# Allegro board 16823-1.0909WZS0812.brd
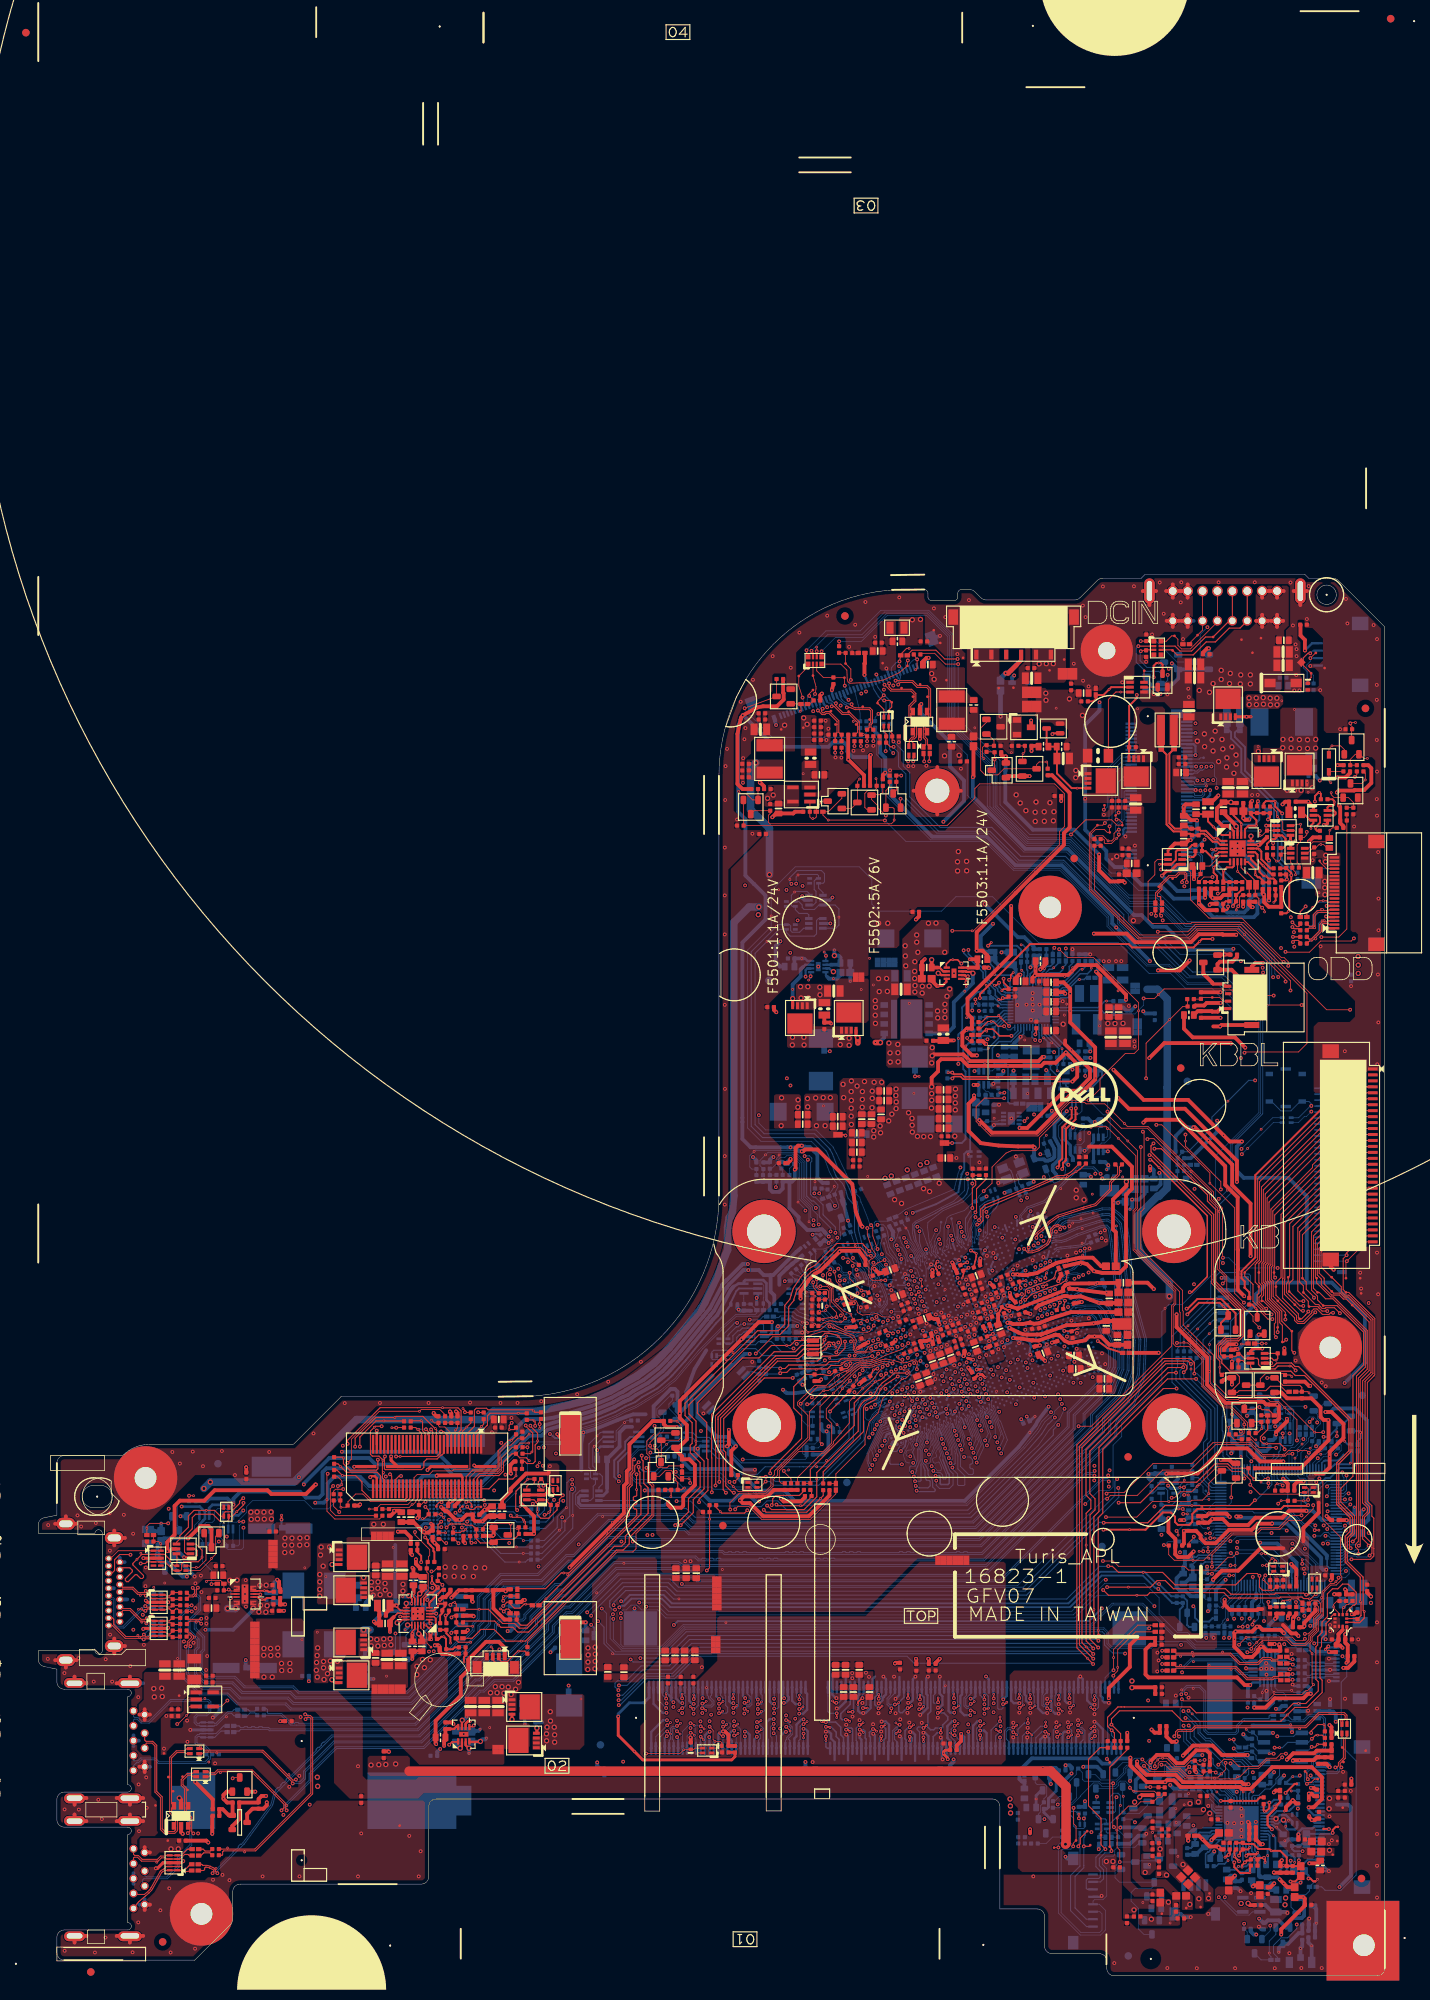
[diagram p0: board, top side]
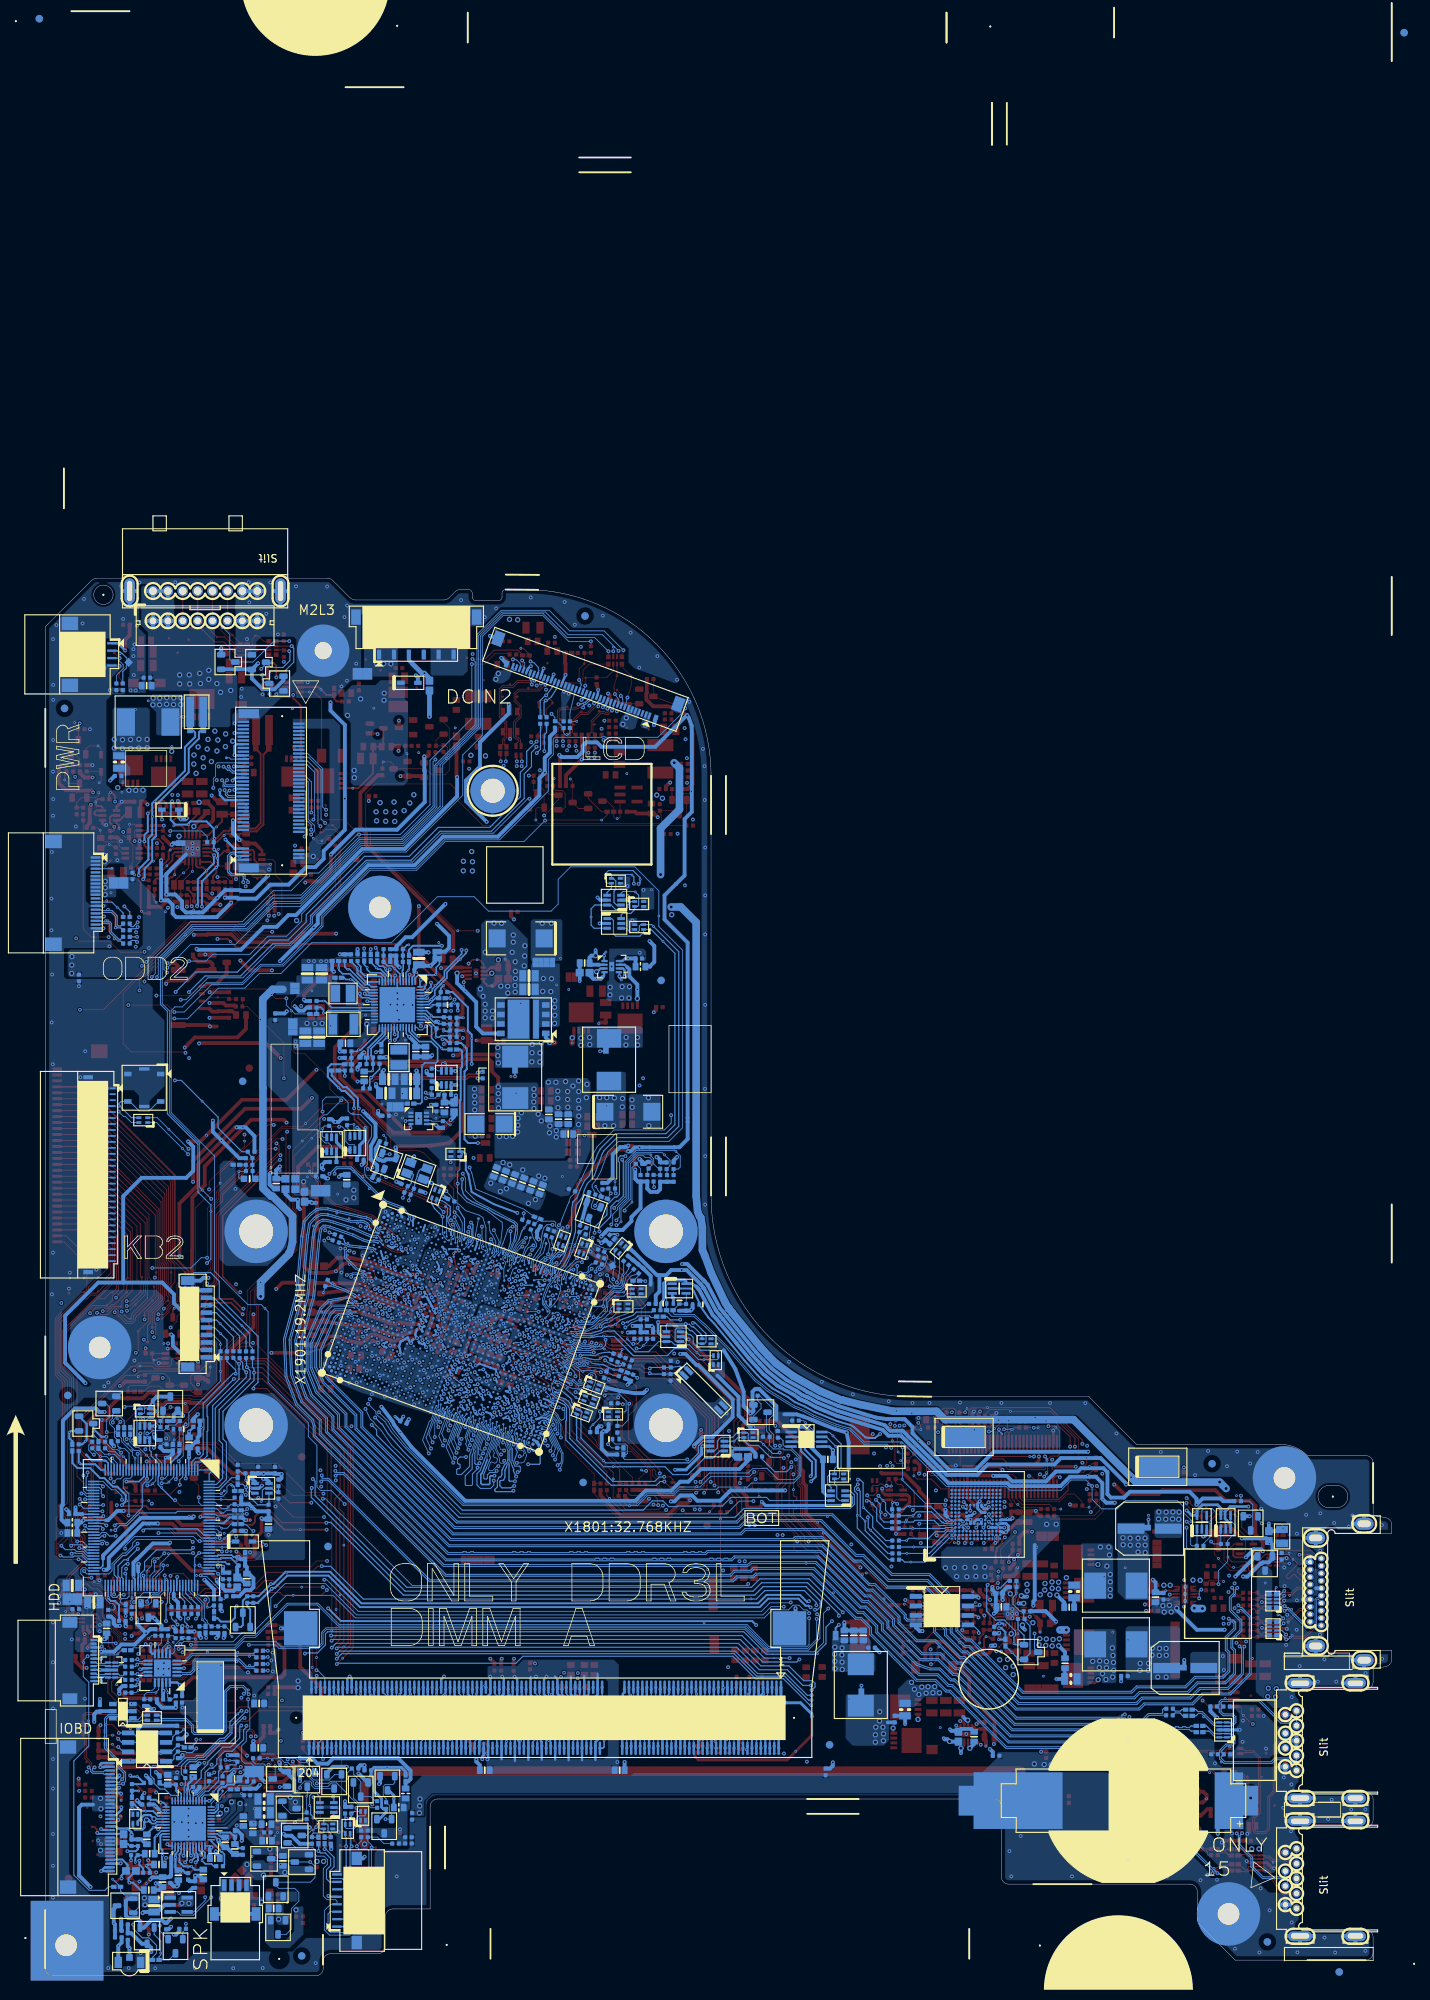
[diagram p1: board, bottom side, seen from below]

Outline 180.7 x 188 mm; copper layers: TOP, L2VCC, L3, L4, L5GND, BOTTOM. Coordinates in mm from the lower left corner of the outline.
Outline path: 0,60.48 0,59.35 7.6,59.35 arc(8.1,59.85) 8.6,59.35 8.6,43.65 arc(8.1,43.15) 7.6,43.65 0,43.65 0,42.47 arc(0.23,41.84) 0.8,41.49 2.5,41.15 2.5,39.45 arc(2.79,38.74) 3.5,38.45 11.99,38.45 arc(12.49,37.95) 11.99,37.45 11.99,25.65 arc(12.49,25.15) 11.99,24.65 3.5,24.65 arc(2.79,24.36) 2.5,23.65 2.5,20.95 arc(2.79,20.24) 3.5,19.95 11.99,19.95 arc(12.49,19.45) 11.99,18.95 11.99,7.15 arc(12.49,6.65) 11.99,6.15 3.5,6.15 arc(2.79,5.86) 2.5,5.15 2.5,3.1 arc(2.79,2.39) 3.5,2.1 21,2.1 25.81,6.91 arc(26.02,7.23) 26.1,7.61 26.1,11.3 arc(26.39,12.01) 27.1,12.3 51.4,12.3 arc(52.11,12.59) 52.4,13.3 52.4,22.72 arc(52.69,23.43) 53.4,23.72 128.05,23.72 arc(128.76,23.43) 129.05,22.72 129.05,8.97 134.05,8.97 arc(134.76,8.68) 135.05,7.97 135.05,3.97 arc(135.34,3.26) 136.05,2.97 142.4,2.97 arc(143.11,2.68) 143.4,1.97 143.4,1 arc(143.69,0.29) 144.4,0 179.7,0 arc(180.41,0.29) 180.7,1 180.7,181 174.49,187.21 arc(174.17,187.42) 173.79,187.5 170.5,187.5 170,188 148.5,188 148,187.5 142.81,187.5 arc(142.43,187.42) 142.11,187.21 139.79,184.89 arc(139.47,184.68) 139.09,184.6 127.21,184.6 arc(126.83,184.68) 126.51,184.89 125.69,185.71 arc(125.37,185.92) 124.99,186 123.9,186 arc(123.55,185.85) 123.4,185.5 123.4,185 arc(123.25,184.65) 122.9,184.5 119.9,184.5 arc(119.55,184.65) 119.4,185 119.4,185.5 arc(119.25,185.85) 118.9,186 116.35,186 arc(98.67,178.68) 91.35,161 91.35,104.7 arc(83.44,85.61) 64.35,77.7 40.63,77.7 34.23,71.3 14.9,71.3 arc(12.96,70.91) 11.33,69.8 3.5,69.8 arc(2.79,69.51) 2.5,68.8 2.5,61.8 0.8,61.46 arc(0.23,61.11) 0,60.48 ; 7.4,65.8 8.4,65.8 arc(9.9,64.3) 8.4,62.8 7.4,62.8 arc(5.9,64.3) 7.4,65.8 ; 95.15,99.88 arc(97.4,102.13) 99.65,99.88 arc(97.4,97.63) 95.15,99.88 ; 95.15,73.88 arc(97.4,76.13) 99.65,73.88 arc(97.4,71.63) 95.15,73.88 ; 150.15,99.88 arc(152.4,102.13) 154.65,99.88 arc(152.4,97.63) 150.15,99.88 ; 150.15,73.88 arc(152.4,76.13) 154.65,73.88 arc(152.4,71.63) 150.15,73.88 ; 171.6,185.3 arc(172.9,186.6) 174.2,185.3 arc(172.9,184) 171.6,185.3

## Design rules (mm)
constraint set DEFAULT: min track width 0.127, pair gap 0.102
net group ALWON: nets 3V_S5_EN 5V_S5_EN
net group BT_USB20_N: nets BT_USB20_N USB_CON_PN5
net group BT_USB20_P: nets BT_USB20_P USB_CON_PP5
net group CARD1_USB20_N: nets CARD1_USB20_N USB_CON_PN6
net group CARD1_USB20_P: nets CARD1_USB20_P USB_CON_PP6
net group CHARGER_10MIL_VIA_25MIL: nets PWR_CHG_CSON_1 PWR_CHG_CSOP_1
net group COMP_DRAM: nets SM_RCOMP_0 SM_RCOMP_1
net group COMP_USB: nets USB_RCOMP USB_SSIC_RCOMP
net group DDR3_CHA_CTRL-MW: nets M_A_CS#0 M_A_CS#1
net group DDR3L_CHA_CTRL_CKE: nets M_A_CKE0 M_A_CKE1
net group DDR3L_CHA_CTRL_ODT: nets M_A_ODT0 M_A_ODT1
net group EC_SPI_CLK: nets EC_SPI_CLK SPI_CLK_ROM
net group EC_SPI_CS0#: nets EC_SPI_CS0# SPI_CS_ROM_N0_R
net group EC_SPI_MISO: nets EC_SPI_MISO SPI1_SO_ROM_R
net group EC_SPI_MOSI: nets EC_SPI_MOSI SPI_SI_ROM
net group EDP_AUX_CON_N: nets EDP_AUX_CON_N EDP_AUX_CPU_N
net group EDP_AUX_CON_P: nets EDP_AUX_CON_P EDP_AUX_CPU_P
net group EDP_TX_CON_N0: nets EDP_TX_CON_N0 EDP_TX_CPU_N0
net group EDP_TX_CON_N1: nets EDP_TX_CON_N1 EDP_TX_CPU_N1
net group EDP_TX_CON_P0: nets EDP_TX_CON_P0 EDP_TX_CPU_P0
net group EDP_TX_CON_P1: nets EDP_TX_CON_P1 EDP_TX_CPU_P1
net group GND_100: nets EC_AGND JDREF
net group GND_400: nets GND_R1 GND_R2
net group HDA_BITCLK_CPU: nets HDA_BITCLK_CPU HDA_CODEC_BITCLK
net group HDA_CODEC_SDIN0: nets HDA_CODEC_SDIN0 HDA_SDIN0_CPU
net group HDA_CODEC_SDOUT: nets HDA_CODEC_SDOUT HDA_SDOUT_CPU
net group HDA_CODEC_SYNC: nets HDA_CODEC_SYNC HDA_SYNC_CPU
net group HDMI_CLK_CON: nets HDMI_CLK_CON HDMI_CLK_CPU
net group HDMI_DATA_CON: nets HDMI_DATA_CON HDMI_DATA_CPU
net group HDMI_DATA_CON_N0: nets HDMI_DATA_CON_N0 HDMI_DATA_CPU_N0
net group HDMI_DATA_CON_N1: nets HDMI_DATA_CON_N1 HDMI_DATA_CPU_N1
net group HDMI_DATA_CON_N2: nets HDMI_DATA_CON_N2 HDMI_DATA_CPU_N2
net group HDMI_DATA_CON_N3: nets HDMI_DATA_CON_N3 HDMI_DATA_CPU_N3
net group HDMI_DATA_CON_P0: nets HDMI_DATA_CON_P0 HDMI_DATA_CPU_P0
net group HDMI_DATA_CON_P1: nets HDMI_DATA_CON_P1 HDMI_DATA_CPU_P1
net group HDMI_DATA_CON_P2: nets HDMI_DATA_CON_P2 HDMI_DATA_CPU_P2
net group HDMI_DATA_CON_P3: nets HDMI_DATA_CON_P3 HDMI_DATA_CPU_P3
net group I2C_DATA: nets DBG_I2C_SDA_LB I2C7_SDA_CPU
net group ISH_GP: nets GSENSOR_CS GSENSOR_SDO
net group OTG: nets USB2_OTG_ID USB2_VBUS_SNS
net group OTHER_4_CLASS: nets 5V_DDC_HDMI1 5V_DDC_HDMI2
net group OTHER_10: nets CAP_LED CAP_LED_Q
net group POWER_15M: nets 3D3V_TP_S5_R Q6205_Q
net group PSID_4M: nets PS_ID PSID
net group SMBUS_50-MWS: nets TP_I2C_CLK_C TP_I2C_DATA_C
net group SPI_CLK_ROM_CPU: nets SPI_CLK_ROM_CPU SPI_CLK_ROM_R1
net group SPI_CS_CPU_N0: nets SPI_CS_CPU_N0 SPI_CS_ROM_N0_R1
net group SPI_HOLD_ROM: nets SPI_HOLD_ROM SPI_HOLD_ROM_R
net group SPI_SI_ROM_CPU: nets SPI_SI_ROM_CPU SPI_SI_ROM_R1
net group SPI_SO_ROM: nets SPI_SO_ROM SPI_SO_ROM_R1
net group SPI_WP_ROM: nets SPI_WP_ROM SPI_WP_ROM_R
net group TS_USB20_N: nets TS_USB20_N USB_PN4_TPNL
net group TS_USB20_P: nets TS_USB20_P USB_PP4_TPNL
net group USB1_USB20_N: nets USB1_USB20_N USB_CON_PN1
net group USB1_USB20_P: nets USB1_USB20_P USB_CON_PP1
net group USB1_USB30_RX_CON_N: nets USB1_USB30_RX_CON_N USB1_USB30_RX_N
net group USB1_USB30_RX_CON_P: nets USB1_USB30_RX_CON_P USB1_USB30_RX_P
net group USB2_CON_USB20_N: nets USB2_CON_USB20_N USB2_USB20_N
net group USB2_CON_USB20_P: nets USB2_CON_USB20_P USB2_USB20_P
net group USB2_USB30_RX_CON_N: nets USB2_USB30_RX_CON_N USB2_USB30_RX_N
net group USB2_USB30_RX_CON_P: nets USB2_USB30_RX_CON_P USB2_USB30_RX_P
net group USB3_CON_USB20_N: nets USB3_CON_USB20_N USB3_USB20_N
net group USB3_CON_USB20_P: nets USB3_CON_USB20_P USB3_USB20_P
net group WLAN_CPU_TX_N: nets WLAN_CPU_TX_N WLAN_PCIE_TX_N
net group WLAN_CPU_TX_P: nets WLAN_CPU_TX_P WLAN_PCIE_TX_P
net group BKLT_EDP-MW: nets BKLT_CTRL EC_BRIGHTNESS EDP_BLCTRL_CPU EDP_VDDEN_CPU L_BKLT_CTRL L_BKLT_CTRL_B L_BKLT_EN_EC LCD_BRIGHTNESS LVDS_VDD_EN LVDS_VDD_EN_B LVDS_VDD_EN_R
net group CHARGER_10MIL: nets BOOST_MODE# PWR_CHG_CMPIN_R PWR_CHG_CMPIN_RR PWR_CHG_IFAULT PWR_CHG_ILIM PWR_CHG_IOUT
net group CHARGER_20MIL_CLASS: nets PWR_CHG_BTST_R
net group CLK_19D2M_32D768_CPU-MW: nets SUSCLK XTL_19D2M_X1_CPU XTL_19D2M_X2_CPU XTL_32K_X1_CPU XTL_32K_X2_CPU
net group CLK_LPC-MW: nets CLK_TP_SIO LPC_AD_CPU_P0 LPC_AD_CPU_P1 LPC_CLK_CPU_P0 LPC_CLK_CPU_P1 LPC_CLK_DBG LPC_CLK_KBC
net group CMP: nets PURE_HW_SHUTDOWN# THERM_SYS_SHDN# VD_IN1 VD_OUT1#
net group CPU_SIDE-MW: nets 1D8V_S0_EN AC_PRESENT_KBC AD_IA DBC_EN DBC_EN_C DBC_EN_R DDR_DRAMRST# DDR_DRAMRST#_R EDP_BLEN_CPU EDP_HPD_CPU_D GP_SSP0_FS1 H_PROCHOT_EC HDMI_DET_CPU# HDMI_HPD_G HPD_HDMI_CON INT_TP#_CONN PCIE_WAKE0_CPU PCIE_WAKE0_CPU# PCIE_WAKE1_CPU PCIE_WAKE2_CPU PCIE_WAKE3_CPU PM_PWRBTN# PM_PWRBTN#_CPU PM_RSMRST# PM_SLP_S3# PM_SLP_S4# PM_WAKE# PROCHOT#_CPU_R RUN_ON# RUN_ON_R SIO_EXT_SCI# SIO_EXT_SMI# SIO_SLP_S3# SIO_SLP_S4# SOC_PWROK_CPU SOC_RUNTIME_SCI# SUS_PWRDN_ACK SYS_PWROK SYS_PWROK_G TP_IN#_CPU TP_IN#_CPU_D WIFI_RF_EN WLAN_CLKREQ_D
net group DDR3_CHA_CMD-MW: nets M_A_A0 M_A_A1 M_A_A2 M_A_A3 M_A_A4 M_A_A5 M_A_A6 M_A_A7 M_A_A8 M_A_A9 M_A_A10 M_A_A11 M_A_A12 M_A_A13 M_A_A14 M_A_A15
net group DDR3_CHA_CMD_OTHER: nets M_A_CAS# M_A_RAS# M_A_WE#
net group DDR3_CHA_DATA-MW: nets M_A_DQ56 M_A_DQ57 M_A_DQ58 M_A_DQ59 M_A_DQ60 M_A_DQ61 M_A_DQ62 M_A_DQ63
net group DDR3L_CHA_CMD_BS: nets M_A_BS0 M_A_BS1 M_A_BS2
net group DDR3L_CHA_DATA_0_7: nets M_A_DQ0 M_A_DQ1 M_A_DQ2 M_A_DQ3 M_A_DQ4 M_A_DQ5 M_A_DQ6 M_A_DQ7
net group DDR3L_CHA_DATA_8_15: nets M_A_DQ8 M_A_DQ9 M_A_DQ10 M_A_DQ11 M_A_DQ12 M_A_DQ13 M_A_DQ14 M_A_DQ15
net group DDR3L_CHA_DATA_16_23: nets M_A_DQ16 M_A_DQ17 M_A_DQ18 M_A_DQ19 M_A_DQ20 M_A_DQ21 M_A_DQ22 M_A_DQ23
net group DDR3L_CHA_DATA_24_31: nets M_A_DQ24 M_A_DQ25 M_A_DQ26 M_A_DQ27 M_A_DQ28 M_A_DQ29 M_A_DQ30 M_A_DQ31
net group DDR3L_CHA_DATA_32_39: nets M_A_DQ32 M_A_DQ33 M_A_DQ34 M_A_DQ35 M_A_DQ36 M_A_DQ37 M_A_DQ38 M_A_DQ39
net group DDR3L_CHA_DATA_40_47: nets M_A_DQ40 M_A_DQ41 M_A_DQ42 M_A_DQ43 M_A_DQ44 M_A_DQ45 M_A_DQ46 M_A_DQ47
net group DDR3L_CHA_DATA_48_55: nets M_A_DQ48 M_A_DQ49 M_A_DQ50 M_A_DQ51 M_A_DQ52 M_A_DQ53 M_A_DQ54 M_A_DQ55
net group DDR_VREF: nets M_A_VREFCA_CPU M_A_VREFDQ_CPU VREF_CA VREF_DQ
net group EMMC_DATA_CMD: nets EMMC_CMD EMMC_CMD_R EMMC_DATA_0 EMMC_DATA_0_R EMMC_DATA_1 EMMC_DATA_1_R EMMC_DATA_2 EMMC_DATA_2_R EMMC_DATA_3 EMMC_DATA_3_R EMMC_DATA_4 EMMC_DATA_4_R EMMC_DATA_5 EMMC_DATA_5_R EMMC_DATA_6 EMMC_DATA_6_R EMMC_DATA_7 EMMC_DATA_7_R EMMC_E9 EMMC_E10 EMMC_F10 EMMC_K10 EMMC_RESET# EMMC_RST_N EMMC_VDDI
net group EMMC_DATA_CMD_CLK: nets EMMC_CLK EMMC_CLK_R EMMC_CLK_RC EMMC_RCLK EMMC_RCLK_R EMMC_RCLK_RC
net group EMMC_RCOMP: nets EMMC_RCOMP
net group FAN_TACH: nets FAN_TACH1
net group FFS: nets HDD_FALL_INT
net group GND_20: nets MIC_GND
net group GPIO: nets DBG_PMU_RSTBTN DBG_TARGET_PRESENT_N DIMM1_SA0 DIMM1_SA1 GP_SSP2_TXD GPIO34_CPU GPIO35_CPU GPIO40_CPU GPIO82_CPU HDD_DEVSLP_R INTRUDER JTAG_PMODE KB_DET# PLT_RST#_DEBUG PM_BATLOW# PM_RSTBTN# PM_SLP_S0# PM_SUS_STAT# PM_SUSCLK SATA_LED#_CPU TP_INT#_EC TS#_DIMM0_1
net group HDD_SATA_RX_N: nets HDD_SATA_RX_N SATA3_DRX_CTX_N0 SATA3_DRX_CTX_N0_R SATA3_PRX_DTX_N0_L SATA_RXN0_C
net group HDD_SATA_RX_P: nets HDD_SATA_RX_P SATA3_DRX_CTX_P0 SATA3_DRX_CTX_P0_R SATA3_PRX_DTX_P0_L SATA_RXP0_C
net group HDD_SATA_TX_N: nets HDD_SATA_TX_N SATA3_DTX_CRX_N0 SATA3_DTX_CRX_N0_R SATA3_PTX_DRX_N0_R SATA_TXN0_C
net group HDD_SATA_TX_P: nets HDD_SATA_TX_P SATA3_DTX_CRX_P0 SATA3_DTX_CRX_P0_R SATA3_PTX_DRX_P0_R SATA_TXP0_C
net group I2C_CLK: nets DBG_I2C_SCL_LB I2C7_SCL_CPU PMIC_I2C_SCL
net group I2C_CLK_CLASS: nets I2C3_SCL_CPU TP_I2C_CLK TP_I2C_CLK_D
net group I2C_DATA_CLASS: nets I2C3_SDA_CPU TP_I2C_DATA TP_I2C_DATA_D
net group KB: nets KSI0 KSI1 KSI2 KSI3 KSI4 KSI5 KSI6 KSI7 KSO0 KSO1 KSO2 KSO3 KSO4 KSO5 KSO6 KSO7 KSO8 KSO9 KSO10 KSO11 KSO12 KSO13 KSO14 KSO15 KSO16
net group KBC_XTAL: nets DBG_CFG6
net group LED: nets BATT_WHITE_LED# BATT_WHITE_LED_R# CHG_AMBER_LED# CHG_AMBER_LED_R#
net group LED_20MIL: nets AMBER_LED_BAT BAT_AMBER BAT_WHITE WHITE_LED_BAT
net group LPC: nets CLKRUN# INT_SERIRQ INT_SERIRQ_KBC INT_SERIRQ_OE LPC_AD_CPU_P2 LPC_AD_CPU_P3 LPC_FRAME#_CPU LPC_FRAME#_DEBUG LPC_LAD0_C LPC_LAD0_R LPC_LAD1_C LPC_LAD1_R LPC_LAD2_C LPC_LAD2_R LPC_LAD3_C LPC_LAD3_R PM_CLKRUN#_EC SERIRQ
net group NOISE_SENSITIVE_GPIO: nets DBG_PMU_PLTRST H_PROCHOT# PLT_RST# PLTRST#_CPU
net group OTHER_4: nets 3V_5V_PWRGD AC_DIS AC_IN# AC_IN_KBC AC_IN_KBC# AD_IA_HW AD_IA_HW2 ALERT# BLON_OUT_C BLUETOOTH_EN_KBC BOOT_HALT_N CAP_LED# CAP_LED_R# COMBO-GPI DBG_PMU_PWRBTN DC_DET DP_HPD0_C DP_HPD0_G DVSS E51_RX1 E51_RX2 E51_TX1 E51_TX2 EC_SMI# EC_SMI#_SOC ECRST# H_A20GATE H_RCIN# INT_SPK_1 INT_SPK_R KBC_ON#_GATE KBC_ON#_GATE_L KBC_PECI KBC_PWRBTN# LCD_TST LCD_TST_C LCD_TST_EN LCD_TST_KBC LID_CLOSE# LVDS_VDD_EN_KBC PANEL_BKEN_EC PANEL_BKEN_EC_KBC PBAT_PRES1# PBAT_PRES# PCB_VER_AD PD4404_A PD4404_K PMIC_EN_KBC PMIC_PWRGD PMIC_THERMTRIP# PQ3802_1 PQ4408_2 PQ4408_6 PQ4409_C PQ4409_E PQ4410_2 PQ4410_3 PQ4410_5 PQ4410_6 PQ4414_D PQ4414_G PRO_SP PROJECT_ID1 PROJECT_ID2 PSID_DISABLE#_R_C PSL_IN1# PSL_IN2# PSL_OUT# PTP_DIS# RTC_DET# SATA3_EQ1_HDD SATA3_EQ2_HDD SATA_LED SD_AMP SD_AMP# SD_AMP_R SIO_SLP_S3 SIO_SLP_S4 SUS_PWR_ACK_R SYS_PRES1# T_CRIT# TOUCH_INT_CPU TOUCH_PANEL_EN TOUCH_RST_CPU TP_DISABLE#_R TP_EN# TP_ON#_GATE TPNL_EN TRST_PD UART2_RTS# USB_OC#0 USB_OC#1 USB_PWR_EN#
net group OTHER_4_2: nets 3V_EN AC_PRESENT BOARD_ID2 CT#_U4002 EC_MUTE# GFX_CLKREQ_CPU# HDD_DEW1 HDD_DEW2 KB_LED_BL_DET_R KB_LED_DET_C LAN_CLKREQ_CPU# LID_CLOSE#_C NMI_SMI_DBG#_CPU PANEL_SIZE_ID PANEL_SIZE_ID_CONN PCIE_CLKREQ1_CPU# PD# PEG_CLKREQ_WLAN# PMIC_THERMTRIP#_KBC PWR_5V_VCLK RSMRST#_KBC RSMRST_IN_PMIC SATA3_DE1_HDD SATA3_DE2_HDD SATA_DEVSLP_HDD_CPU TP_RESET VRAM_ID1 WLAN_CLKREQ_CPU#
net group OTHER_4MIL_8MIL: nets E51_TXD
net group OTHER_6: nets S5_ENABLE
net group OTHER_8: nets COMP2 COMP2_P FB_VNN FBL_VCCGI FBL_VDDQ FBL_VNN PMIC_IRQ PMIC_PWROK_KBC PMIC_RSMRST#
net group OTHER_12: nets CBN CBP CPVEE LDO1_CAP LDO2_CAP LDO3_CAP V3D3_STB
net group P27_AUDIO_ANALOG: nets AUD_HP1_JACK_L AUD_HP1_JACK_L1 AUD_HP1_JACK_R AUD_HP1_JACK_R1 AUD_PC_BEEP_3246 AUD_PC_BEEP_C AUD_PC_BEEP_R AUD_PORTA_L_R_B AUD_PORTA_R_R_B AUD_SENSE AUD_SENSE_A AUD_VREF BEEP HDA_SPKR HDA_SPKR_R JACK_PLUG KBC_BEEP_R LINE1-L_C LINE1-L_R LINE1_L LINE1_R LINE1_VREFO_L LINE1_VREFO_R
net group PLATFORM: nets CAMERA_DET# CAMERA_DET#_R KBC_PWRBTN#_C PQ3809_D SATA_ODD_DA#_C SATA_ODD_DA#_C2 SATA_ODD_PRSNT# SATA_ODD_PRSNT#_CPU SATA_ODD_PRSNT#_D SATA_ODD_PRSNT#_R SATA_ODD_PRSNT#_R2
net group POWER_8: nets PWR_1D8V_FB PWR_1D24V_FB PWR_COMP2 PWR_CSDIS1 PWR_CSDIS2 PWR_DDRSEL PWR_FB2 PWR_IRQ# PWR_OCSET6 PWR_PMIC_EN PWR_PWROK PWR_RSMEST# PWR_SLP_S0# PWR_SLP_S3# PWR_SLP_S4# PWR_THERMTRIP# PWR_VCCGI_EN PWR_VCCGI_ISEN PWR_VCCGI_PWM PWR_VCCRAM_FB PWR_VDDQ_EN PWR_VDDQ_FB PWR_VDDQ_PWM PWR_VIN_CT PWR_VNN_EN PWR_VNN_FB PWR_VNN_PWM PWR_VO2 PWR_VSS PWR_VSYS PWR_VTT_SEN
net group POWER_8_CLASS: nets PWR_VCCGI_SNUB PWR_VDDQ_SNUB PWR_VNN_SNUB
net group POWER_10: nets 3D3V_S0_CT 5V_S0_CT +3.3V_1.8V_DVDD-IO +3V_1D5V_AVDD +3V_AVDD FAN1_DAC_1 MIC_CAP PWR_3D3V_CS2 PWR_3D3V_EN2 PWR_3D3V_FB2 PWR_3D3V_FB2_R PWR_5V_CS1 PWR_5V_FB1_R PWR_CHG_ACDET PWR_CHG_ACOK PWR_CHG_CMPIN PWR_CHG_REGN PWR_CHG_VCC
net group POWER_10_CLASS: nets PWR_CHG_BTST
net group POWER_10_VIA: nets AD+_G_1 AD+_G_2 DC_IN_D PWR_CHG_SRN PWR_CHG_SRP
net group POWER_10M_POWER: nets 3V_FEEDBACK AC_IN#_G AD_OFF_L AD_OFF_R PWR_5V_EN1 PWR_5V_FB1 PWR_CHG_CMPOUT
net group POWER_20: nets 0D675V_S0_DISCHG 1D8V_S0_DISCHG 1D35V_S3_DISCHG 3D3V_G_VDD_S0 3D3V_VCCRTC +5V_AVDD +RTC_PWR EC_AVCC EC_VCC1V8 EC_VTT EMMC_VCC EMMC_VCCQ KBC_VCC KBC_VCC1D8V KBC_VCORF PWR_3D3V_VBST2 PWR_3D3V_VBST2_1 PWR_5V_VBST1 PWR_5V_VBST1_1 PWR_5V_VO1 PWR_VCC PWR_VCCGI_VCC PWR_VDDQ_VCC PWR_VNN_VCC RTC_DET#_G SPI1_VCC_1D8V SPI_VCC_1D8V
net group POWER_20M_POWER: nets 3D3V_PWR_2 5V_PWR_2 +5V_KB_BL BKLGT_PWM CPVDD KB_BL_CTRL# PWR_3D3V_SNUB PWR_5V_SNUB
net group POWER_30_CLASS: nets PWR_VCCGI_BOOT PWR_VCCGI_BOOT_A PWR_VCCGI_HG PWR_VCCGI_LG PWR_VDDQ_BOOT PWR_VDDQ_BOOT_A PWR_VDDQ_HG PWR_VDDQ_LG PWR_VNN_BOOT PWR_VNN_BOOT_A PWR_VNN_HG PWR_VNN_LG
net group POWER_40M_POWER: nets 5V_HDMI_R_S0 PWR_3D3V_DRVH2 PWR_5V_DRVH1
net group POWER_60: nets 1D24V_AUD_ISH_PLL 1D24V_DSI_CSI 1D24V_GLML 1D24V_USB2 1P8U 3D3V_1D8V_GSEN2 PWR_VTT
net group POWER_120: nets 1D05V_FHV0 1D05V_FHV1 1D05V_FUSE
net group PSID_25MIL: nets PS_ID_R
net group PWR_PHA: nets PWR_VCCGI_PHA PWR_VDDQ_PHA PWR_VNN_PHA
net group RCOMP: nets GPIO_RCOMP MCSI_RCOMP_1 MCSI_RCOMP_2 MDSI_RCOMP PCIE_REF_CLK_RCOMP PMU_RCOMP
net group REF_10: nets KBC_VBKUP
net group RTC-MW: nets BVCCRTC_EXTPAD
net group SENSOR: nets FALL_INT2 FFS_INT2 FFS_INT2_Q
net group SIGNAL_V_F_4MIL: nets HDD_DEVSLP
net group SIGNAL_V_F_5MIL: nets DGPU_PWROK
net group SMBUS_CLK-MW: nets AVS_DMIC_CLK AVS_DMIC_DATA DMIC_CLK DMIC_CLK_C DMIC_CLK_C# DMIC_CLK_D DMIC_CLK_R DMIC_DATA_C# DMIC_DATA_D NCT_CLK PBAT_SMBCLK1 PCH_SMB_CLK PWR_CHG_BAT_SCL SMB_ALERT#_CPU SMB_CLK SMB_CLK_CPU SMBCLK1 TP_CLK_C
net group SMBUS_DAT-MW: nets DAT_TP_SIO DMIC_DATA DMIC_DATA_C DMIC_DATA_R NCT_DATA PBAT_SMBDAT1 PCH_SMB_DATA PMIC_I2C_SDA PWR_CHG_BAT_SDA SMB_DATA SMB_DATA_CPU SMBDA1 TP_DATA_C
net group SPI_SIDE: nets SPI1_HOLD_ROM_R SPI1_WP_ROM_R UART2_RXD UART2_TXD
net group STRAP_PIN: nets DFX_MSR_STRAP GPIO36_VCCIO_LEVEL GPIO39_TXE_BPS GPIO43_EMMC_BOOT GPIO44_SPI_BOOT GPIO47_DNXFW GPIO78_SMB_LEVEL GPIO88_PMU_LEVEL GPIO92_SMB_NRB GPIO110_LPC_LEVEL GPIO111_BBS GPIO118_FLASH_OVR GPIO120_BIOS_SWAP ME_FWP_EC_CPU
net group T8: nets VD_IN1_C
net group THERM_10MIL: nets VD1_EN#
net group USB1_USB30_TX_CON_N: nets USB1_USB30_TX_CON_N USB1_USB30_TX_N USB1_USB30_TX_N_R
net group USB1_USB30_TX_CON_P: nets USB1_USB30_TX_CON_P USB1_USB30_TX_P USB1_USB30_TX_P_R
net group USB2_USB30_TX_CON_N: nets USB2_USB30_TX_CON_N USB2_USB30_TX_N USB2_USB30_TX_N_R
net group USB2_USB30_TX_CON_P: nets USB2_USB30_TX_CON_P USB2_USB30_TX_P USB2_USB30_TX_P_R
net group XDP-MW: nets CFG0 CFG1 CFG2 CFG3 CFG4 CFG5 CFG6 CFG7 DBG_CFG7 DBG_PTI_CLK0 DBG_RSMRST DBG_UART_RXD DBG_XDP_PRDY# DBG_XDP_PREQ# DBG_XDP_TDI DBG_XDP_TDO DBG_XDP_TMS DBG_XDP_TRST# LPSS_UART1_TXD XDP_PRDY# XDP_PREQ# XDP_TDI XDP_TDO XDP_TMS XDP_TRST# XDP_UART_RXD_CPU
net group XDP_CLK: nets DBG_XDP_TCK XDP_PTI_CLK0 XDP_TCK
net group XTAL-MW: nets RTC_RST# RTC_TEST# RTCRST_ON

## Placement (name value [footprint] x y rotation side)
AFTP2501  AFTE14P-GP  [AFTE14P-75]  48.5 20.14 0 top
AFTP2502  AFTE14P-GP  [AFTE14P-75]  23.35 19.94 0 top
AFTP2901  AFTE14P-GP  [AFTE14P-75]  150.78 8.33 0 top
AFTP2902  AFTE14P-GP  [AFTE14P-75]  154.06 9.1 0 top
AFTP2903  AFTE14P-GP  [AFTE14P-75]  155.99 9.22 0 top
AFTP2904  AFTE14P-GP  [AFTE14P-75]  157.18 11.05 0 top
AFTP2908  AFTE14P-GP  [AFTE14P-75]  169.15 23.12 0 top
AFTP2909  AFTE14P-GP  [AFTE14P-75]  168.89 25.76 0 top
AFTP3501  AFTE14P-GP  [AFTE14P-75]  18.9 37.59 0 top
AFTP3502  AFTE14P-GP  [AFTE14P-75]  18.09 24.77 0 top
AFTP3503  AFTE14P-GP  [AFTE14P-75]  17.46 26.67 0 top
AFTP3504  AFTE14P-GP  [AFTE14P-75]  16.87 29.85 0 top
AFTP3505  AFTE14P-GP  [AFTE14P-75]  15.73 22.86 0 top
AFTP3506  AFTE14P-GP  [AFTE14P-75]  20.02 24.94 0 top
AFTP3507  AFTE14P-GP  [AFTE14P-75]  17.38 18.14 0 top
AFTP3508  AFTE14P-GP  [AFTE14P-75]  19.36 26.72 0 top
AFTP4301  AFTE14P-GP  [AFTE14P-75]  135.72 175.16 0 top
AFTP4302  AFTE14P-GP  [AFTE14P-75]  164.09 179.48 0 top
AFTP4303  AFTE14P-GP  [AFTE14P-75]  152.48 179.78 0 top
AFTP4304  AFTE14P-GP  [AFTE14P-75]  152.23 177.83 0 top
AFTP4305  AFTE14P-GP  [AFTE14P-75]  155.58 179.88 0 top
AFTP4306  AFTE14P-GP  [AFTE14P-75]  162.95 177.52 0 top
AFTP4307  AFTE14P-GP  [AFTE14P-75]  161.48 179.28 0 top
AFTP4308  AFTE14P-GP  [AFTE14P-75]  157.67 179.63 0 top
AFTP4309  AFTE14P-GP  [AFTE14P-75]  124.11 176.84 330 top
AFTP4310  AFTE14P-GP  [AFTE14P-75]  121.05 178.84 330 top
AFTP4311  AFTE14P-GP  [AFTE14P-75]  120.17 180.55 330 top
AFTP4312  AFTE14P-GP  [AFTE14P-75]  130.54 175.14 0 top
AFTP4313  AFTE14P-GP  [AFTE14P-75]  130.87 172.82 0 top
AFTP4314  AFTE14P-GP  [AFTE14P-75]  128.91 172.77 0 top
AFTP4315  AFTE14P-GP  [AFTE14P-75]  137.68 176.61 0 top
AFTP5501  AFTE14P-GP  [AFTE14P-75]  99.7 167.24 330 top
AFTP5502  AFTE14P-GP  [AFTE14P-75]  111.56 168.56 330 top
AFTP5503  AFTE14P-GP  [AFTE14P-75]  110.65 170.28 330 top
AFTP5504  AFTE14P-GP  [AFTE14P-75]  109.76 167.9 330 top
AFTP5505  AFTE14P-GP  [AFTE14P-75]  108.74 169.62 330 top
AFTP5506  AFTE14P-GP  [AFTE14P-75]  106.99 167.9 330 top
AFTP5507  AFTE14P-GP  [AFTE14P-75]  106.38 169.7 330 top
AFTP5508  AFTE14P-GP  [AFTE14P-75]  115.86 172.77 330 top
AFTP5509  AFTE14P-GP  [AFTE14P-75]  117.38 171.63 330 top
AFTP5510  AFTE14P-GP  [AFTE14P-75]  114.54 170.87 330 top
AFTP5511  AFTE14P-GP  [AFTE14P-75]  112.63 170.77 330 top
AFTP5512  AFTE14P-GP  [AFTE14P-75]  110.9 176.07 330 top
AFTP5513  AFTE14P-GP  [AFTE14P-75]  102.06 174.4 330 top
AFTP5514  AFTE14P-GP  [AFTE14P-75]  103.97 174.45 330 top
AFTP5515  AFTE14P-GP  [AFTE14P-75]  103.97 172.52 330 top
AFTP5516  AFTE14P-GP  [AFTE14P-75]  108.34 176.07 330 top
AFTP5517  AFTE14P-GP  [AFTE14P-75]  108.19 174.17 330 top
AFTP5518  AFTE14P-GP  [AFTE14P-75]  118.35 173.28 330 top
AFTP5519  AFTE14P-GP  [AFTE14P-75]  119.33 171.61 330 top
AFTP5520  AFTE14P-GP  [AFTE14P-75]  116.64 175.77 330 top
AFTP5521  AFTE14P-GP  [AFTE14P-75]  121.88 173.84 330 top
AFTP5522  AFTE14P-GP  [AFTE14P-75]  113.32 176.13 330 top
AFTP5523  AFTE14P-GP  [AFTE14P-75]  102.67 167.46 330 top
AFTP6101  AFTE14P-GP  [AFTE14P-75]  144.13 149.81 0 top
AFTP6103  AFTE14P-GP  [AFTE14P-75]  142.15 154.38 0 top
AFTP6104  AFTE14P-GP  [AFTE14P-75]  145.47 154.38 0 top
AFTP6106  AFTE14P-GP  [AFTE14P-75]  150.38 146.13 90 top
AFTP6107  AFTE14P-GP  [AFTE14P-75]  152.23 147.22 90 top
AFTP6108  AFTE14P-GP  [AFTE14P-75]  143.8 153.42 0 top
AFTP6401  AFTE14P-GP  [AFTE14P-75]  171.46 177.5 0 top
AFTP6402  AFTE14P-GP  [AFTE14P-75]  169.39 179.84 0 top
AFTP6403  AFTE14P-GP  [AFTE14P-75]  172.63 175.47 0 top
AFTP6404  AFTE14P-GP  [AFTE14P-75]  170.82 174.78 0 top
AFTP6501  AFTE14P-GP  [AFTE14P-75]  157.56 129.37 90 top
AFTP6502  AFTE14P-GP  [AFTE14P-75]  172.45 89.92 0 top
AFTP6503  AFTE14P-GP  [AFTE14P-75]  161.91 94.36 0 top
AFTP6505  AFTE14P-GP  [AFTE14P-75]  168.64 90.05 0 top
AFTP6506  AFTE14P-GP  [AFTE14P-75]  163.81 92.46 0 top
AFTP6507  AFTE14P-GP  [AFTE14P-75]  169.65 93.6 0 top
AFTP6508  AFTE14P-GP  [AFTE14P-75]  168.23 86.49 0 top
AFTP6510  AFTE14P-GP  [AFTE14P-75]  165.84 94.36 0 top
AFTP6511  AFTE14P-GP  [AFTE14P-75]  173.59 93.73 0 top
AFTP6512  AFTE14P-GP  [AFTE14P-75]  167.75 93.73 0 top
AFTP6513  AFTE14P-GP  [AFTE14P-75]  171.56 93.6 0 top
AFTP6515  AFTE14P-GP  [AFTE14P-75]  166.96 85.04 0 top
AFTP6516  AFTE14P-GP  [AFTE14P-75]  163.81 94.36 0 top
AFTP6517  AFTE14P-GP  [AFTE14P-75]  166.1 92.46 0 top
AFTP6518  AFTE14P-GP  [AFTE14P-75]  169.27 88.14 0 top
AFTP6519  AFTE14P-GP  [AFTE14P-75]  175.5 93.6 0 top
AFTP6520  AFTE14P-GP  [AFTE14P-75]  166.35 90.55 0 top
AFTP6521  AFTE14P-GP  [AFTE14P-75]  173.59 91.82 0 top
AFTP6522  AFTE14P-GP  [AFTE14P-75]  170.54 89.79 0 top
AFTP6523  AFTE14P-GP  [AFTE14P-75]  175.5 91.7 0 top
AFTP6524  AFTE14P-GP  [AFTE14P-75]  142.63 18.87 0 top
AFTP6525  AFTE14P-GP  [AFTE14P-75]  136.33 17.2 0 top
AFTP6526  AFTE14P-GP  [AFTE14P-75]  139.28 18.16 90 top
AFTP6527  AFTE14P-GP  [AFTE14P-75]  140.77 19.41 90 top
AFTP6528  AFTE14P-GP  [AFTE14P-75]  141.18 17.53 90 top
AFTP6529  AFTE14P-GP  [AFTE14P-75]  133.1 19.1 0 top
AFTP6530  AFTE14P-GP  [AFTE14P-75]  143.8 17.32 0 top
AFTP6531  AFTE14P-GP  [AFTE14P-75]  177.53 91.57 0 top
AFTP6532  AFTE14P-GP  [AFTE14P-75]  161.91 92.33 0 top
AFTP6533  AFTE14P-GP  [AFTE14P-75]  176.33 89.99 0 top
AFTP6534  AFTE14P-GP  [AFTE14P-75]  167.88 91.82 0 top
AFTP6535  AFTE14P-GP  [AFTE14P-75]  166.33 87 0 top
AFTP6536  AFTE14P-GP  [AFTE14P-75]  169.78 91.7 0 top
AFTP6537  AFTE14P-GP  [AFTE14P-75]  157.69 127.38 0 top
AFTP6538  AFTE14P-GP  [AFTE14P-75]  167.37 88.65 0 top
AFTP6539  AFTE14P-GP  [AFTE14P-75]  164.19 90.55 0 top
AFTP6540  AFTE14P-GP  [AFTE14P-75]  171.69 91.7 0 top
AFTP6565  AFTE14P-GP  [AFTE14P-75]  177.4 93.6 0 top
AFTP6566  AFTE14P-GP  [AFTE14P-75]  157.56 131.27 90 top
AFTP6567  AFTE14P-GP  [AFTE14P-75]  157.56 133.18 90 top
AFTP6601  AFTE14P-GP  [AFTE14P-75]  174.99 30.63 0 top
AFTP6602  AFTE14P-GP  [AFTE14P-75]  175.17 28.68 0 top
AFTP6603  AFTE14P-GP  [AFTE14P-75]  170.01 27.43 0 top
AFTP6604  AFTE14P-GP  [AFTE14P-75]  171.71 26.39 0 top
AFTP6605  AFTE14P-GP  [AFTE14P-75]  173.72 16.26 0 top
AFTP6606  AFTE14P-GP  [AFTE14P-75]  172.5 19.71 0 top
AFTP6607  AFTE14P-GP  [AFTE14P-75]  171.38 12.68 0 top
AFTP6608  AFTE14P-GP  [AFTE14P-75]  174.43 19.99 0 top
AFTP6609  AFTE14P-GP  [AFTE14P-75]  174.33 18.09 0 top
AFTP6610  AFTE14P-GP  [AFTE14P-75]  175.06 22.56 0 top
AFTP6611  AFTE14P-GP  [AFTE14P-75]  167.44 22.23 0 top
AFTP6612  AFTE14P-GP  [AFTE14P-75]  178.14 30.2 0 top
BATT1  ALP-CON8-17-GP-U1  [C144KA-108A7-L-1]  159.25 185.8 0 bottom
BATT2  ACES-CON8-S1-GP  [50312-00841-001]  159.25 181.8 0 bottom
C601  SC1U10V2KX-1GP  [C402H22]  127.9 84.1 20 top
C1001  SC1U10V2KX-1GP  [C402H22]  129.65 93.91 110 top
C1002  SC1U10V2KX-1GP  [C402H22]  128.15 90.37 200 top
C1003  SC1U10V2KX-1GP  [C402H22]  128.67 92.59 290 top
C1004  SC1U10V2KX-1GP  [C402H22]  128.96 91.8 290 top
C1005  SC1U10V2KX-1GP  [C402H22]  128.4 88.6 110 top
C1006  SC1U10V2KX-1GP  [C402H22]  126.78 89.87 20 top
C1007  SC1U10V2KX-1GP  [C402H22]  125.98 92.81 290 top
C1008  SC1U10V2KX-1GP  [C402H22]  126.26 92.04 290 top
C1009  SC1U10V2KX-1GP  [C402H22]  135.24 86.76 200 top
C1010  SC1U10V2KX-1GP  [C402H22]  134.46 86.48 200 top
C1011  SC1U10V2KX-1GP  [C402H22]  124.16 84.25 200 top
C1012  SC1U10V2KX-1GP  [C402H22]  133.54 84.85 20 top
C1013  SC1U10V2KX-1GP  [C402H22]  136.61 85.57 20 top
C1014  SC1U10V2KX-1GP  [C402H22]  138.82 90.63 20 top
C1015  SC1U10V2KX-1GP  [C402H22]  132.04 88.88 110 top
C1016  SC1U10V2KX-1GP  [C402H22]  128.44 85.11 200 top
C1017  SC1U10V2KX-1GP  [C402H22]  123.32 83.92 20 top
C1018  SC1U10V2KX-1GP  [C402H22]  129.47 89.31 200 top
C1019  SC1U10V2KX-1GP  [C402H22]  116.26 90.17 290 top
C1020  SC1U10V2KX-1GP  [C402H22]  121.11 88.24 290 top
C1021  SC1U10V2KX-1GP  [C402H22]  109.8 109.43 270 top
C1022  SC1U10V2KX-1GP  [C402H22]  126.3 88.65 200 top
C1023  SC1U10V2KX-1GP  [C402H22]  125.18 86.62 290 top
C1024  SC1U10V2KX-1GP  [C402H22]  116.01 87.89 290 top
C1025  SC1U10V2KX-1GP  [C402H22]  121.66 112.64 90 top
C1026  SC1U10V2KX-1GP  [C402H22]  116.56 89.36 290 top
C1027  SC1U10V2KX-1GP  [C402H22]  124.25 91.84 200 top
C1028  SC1U10V2KX-1GP  [C402H22]  125.18 90.63 110 top
C1029  SC1U10V2KX-1GP  [C402H22]  122.87 86.92 20 top
C1030  SC1U10V2KX-1GP  [C402H22]  123.65 87.15 20 top
C1101  SC1U10V2KX-1GP  [C402H22]  120.48 84.91 110 top
C1102  SC1U10V2KX-1GP  [C402H22]  118.22 84.2 290 top
C1103  SC1U10V2KX-1GP  [C402H22]  117.94 84.99 290 top
C1104  SC1U10V2KX-1GP  [C402H22]  119.41 86.03 290 top
C1106  SC1U10V2KX-1GP  [C402H22]  131.3 89.94 200 top
C1107  SC1U10V2KX-1GP  [C402H22]  137.95 92.05 110 top
C1108  SC1U10V2KX-1GP  [C402H22]  121.55 86.89 110 top
C1109  SC1U10V2KX-1GP  [C402H22]  121.83 86.12 110 top
C1110  SC1U10V2KX-1GP  [C402H22]  117.51 87.45 20 top
C1111  SC1U10V2KX-1GP  [C402H22]  126.9 85.63 290 top
C1112  SC1U10V2KX-1GP  [C402H22]  133.22 87.21 20 top
C1113  SC1U10V2KX-1GP  [C402H22]  105.24 99.06 40 bottom
C1201  SC10U6D3V3MX-GP  [C603H38]  121.72 27.59 270 bottom
C1202  SC10U6D3V3MX-GP  [C603H38]  108.34 41.05 0 top
C1203  SC10U6D3V3MX-GP  [C603H38]  107.02 41.05 0 top
C1205  SC10U6D3V3MX-GP  [C603H38]  103.61 27.59 90 bottom
C1206  SC1U10V2KX-1GP  [C402H22]  115.65 41.56 180 top
C1207  SC1U10V2KX-1GP  [C402H22]  150.96 32.62 90 top
C1208  SC1U10V2KX-1GP  [C402H22]  150.96 33.5 90 top
C1209  SC1U10V2KX-1GP  [C402H22]  150.35 37.82 90 top
C1210  SC1U10V2KX-1GP  [C402H22]  150.35 38.71 90 top
C1211  SC10U6D3V3MX-GP  [C603H38]  110.17 41.05 0 top
C1212  SC10U6D3V3MX-GP  [C603H38]  152 36.55 270 bottom
C1213  SC1U10V2KX-1GP  [C402H22]  117.84 41.38 180 top
C1214  SC1U10V2KX-1GP  [C402H22]  119.51 41.4 180 top
C1215  SC1U10V2KX-1GP  [C402H22]  120.43 41.4 180 top
C1216  SC10U6D3V3MX-GP  [C603H38]  108.08 38.08 180 top
C1217  SC10U6D3V3MX-GP  [C603H38]  109.41 38.08 180 top
C1218  SC10U6D3V3MX-GP  [C603H38]  111.54 38.08 180 top
C1220  SC10U6D3V3MX-GP  [C603H38]  152.13 30.58 270 bottom
C1223  SCD1U16V2KX-3GP  [C402H22]  150.32 45.32 90 top
C1224  SCD1U16V2KX-3GP  [C402H22]  150.32 44.43 90 top
C1601  SCD1U16V2KX-3GP  [C402H22]  141.7 98.53 290 bottom
C1602  SCD1U16V2KX-3GP  [C402H22]  141.42 99.32 290 bottom
C1801  SC1U10V2KX-1GP  [C402H22]  104.31 91.6 270 top
C1802  SC1U10V2KX-1GP  [C402H22]  104.32 90.76 269.9 top
C1803  SC4P50V2CN-GP  [C402H22]  96.76 82.07 0 bottom
C1804  SC4P50V2CN-GP  [C402H22]  96.78 80.29 180 bottom
C1805  SCD1U16V2KX-3GP  [C402H22]  116.62 83.62 110 top
C1901  SC3D9P50V2CN-1GP  [C402H22]  132.47 106.1 290 bottom
C1902  SC3D9P50V2CN-1GP  [C402H22]  130.82 105.46 110 bottom
C2401  SC22P50V2JN-4GP  [C402H22]  154.87 68.12 0 bottom
C2414  SC2D2U10V3KX-1GP  [C603H36]  177.07 59.41 270 bottom
C2416  SC2D2U10V3KX-1GP  [C603H36]  153.65 53.29 0 bottom
C2417  SCD1U16V2KX-3GP  [C402H22]  156.85 53.65 0 bottom
C2418  SCD1U16V2KX-3GP  [C402H22]  158.38 46.43 180 bottom
C2428  SCD1U16V2KX-3GP  [C402H22]  157.61 50.52 90 bottom
C2429  SCD1U16V2KX-3GP  [C402H22]  168.38 52.25 270 top
C2430  SCD1U16V2KX-3GP  [C402H22]  174.07 61.14 270 top
C2431  SCD1U16V2KX-3GP  [C402H22]  168.13 65.1 270 top
C2432  SCD1U16V2KX-3GP  [C402H22]  160.38 73.64 270 bottom
C2433  SC2D2U10V3KX-1GP  [C603H36]  161.4 71.58 0 bottom
C2436  SCD1U16V2KX-3GP  [C402H22]  154.31 55.04 90 bottom
C2438  SCD1U16V2KX-3GP  [C402H22]  155.94 50.93 270 bottom
C2439  SCD1U16V2KX-3GP  [C402H22]  152.13 67.85 0 bottom
C2440  SCD1U16V2KX-3GP  [C402H22]  156.55 61.24 180 top
C2441  SCD1U16V2KX-3GP  [C402H22]  155.68 61.24 180 top
C2442  SCD1U16V2KX-3GP  [C402H22]  164.8 74.45 90 bottom
C2443  SC1U10V2KX-1GP  [C402H22]  177.07 61.95 270 bottom
C2444  SC1U10V2KX-1GP  [C402H22]  165.77 53.09 90 top
C2445  SCD1U16V2KX-3GP  [C402H22]  173.16 53.72 90 top
C2446  SCD1U16V2KX-3GP  [C402H22]  149.87 67.85 0 bottom
C2447  SCD1U16V2KX-3GP  [C402H22]  164.42 70.87 0 bottom
C2501  SC10U6D3V2MX-3-GP  [C402H22]  57.36 51.28 0 top
C2502  SCD1U16V2KX-3GP  [C402H22]  58.2 51.28 0 top
C2503  SC10U6D3V2MX-3-GP  [C402H22]  172.68 28.88 0 top
C2504  SCD1U16V2KX-3GP  [C402H22]  171.78 28.88 0 top
C2601  SCD1U16V2KX-3GP  [C402H22]  168.81 46.77 90 top
C2602  SC10U6D3V3MX-GP  [C603H38]  75.67 69.29 90 bottom
C2603  SC470P50V2KX-3GP  [C402H22]  153.59 50.48 180 bottom
C2604  SC2200P50V2KX-2GP  [C402H22]  152.78 50.48 180 bottom
C2605  SCD1U16V2KX-3GP  [C402H22]  167.08 52.67 180 top
C2606  SCD1U16V2KX-3GP  [C402H22]  153.32 107.98 270 bottom
C2607  SC100P50V2JN-3GP  [C402H22]  153.35 108.82 270 bottom
C2701  SC4D7U6D3V3KX-GP  [C603H36]  157.94 15.78 90 bottom
C2702  SC4D7U6D3V3KX-GP  [C603H36]  162.85 13.49 0 bottom
C2703  SC1U10V2KX-1GP  [C402H22]  157.31 14.71 90 bottom
C2704  SC1U10V2KX-1GP  [C402H22]  159.9 17.4 0 top
C2705  SC2D2U10V3KX-1GP  [C603H36]  159.49 13.59 0 bottom
C2706  SCD1U16V2KX-3GP  [C402H22]  154.05 24.67 0 bottom
C2707  SC10U6D3V3MX-GP  [C603H38]  152.84 19.76 180 bottom
C2708  SCD1U16V2KX-3GP  [C402H22]  153.21 24.67 0 bottom
C2709  SC10U6D3V3MX-GP  [C603H38]  154.12 20.77 180 bottom
C2710  SCD1U16V2KX-3GP  [C402H22]  163.91 12.91 180 bottom
C2711  SC4D7U6D3V3KX-GP  [C603H36]  164.95 12.58 180 bottom
C2712  SC10U6D3V3MX-GP  [C603H38]  156.55 17.91 0 bottom
C2713  SC10U6D3V3MX-GP  [C603H38]  167.06 18.32 180 bottom
C2714  SCD1U16V2KX-3GP  [C402H22]  159.06 17.4 180 top
C2715  SC4D7U6D3V3KX-GP  [C603H36]  155.25 17.02 180 bottom
C2716  SC4D7U6D3V3KX-GP  [C603H36]  155.3 26.42 270 bottom
C2717  SCD1U16V2KX-3GP  [C402H22]  160.03 23.01 0 top
C2718  SC4D7U6D3V3KX-GP  [C603H36]  160.84 27.33 0 bottom
C2719  SCD1U16V2KX-3GP  [C402H22]  163.16 26.1 0 bottom
C2720  SCD1U16V2KX-3GP  [C402H22]  169.07 25.28 180 bottom
C2721  SCD1U16V2KX-3GP  [C402H22]  154.19 16.69 180 bottom
C2722  SC22P50V2JN-4GP  [C402H22]  154.92 29.16 180 bottom
C2723  SC10U6D3V3MX-GP  [C603H38]  164.26 26.31 180 bottom
C2728  SCD1U16V2KX-3GP  [C402H22]  150.9 19.24 270 bottom
C2729  SC10U6D3V3MX-GP  [C603H38]  150.94 18.12 270 bottom
C2901  SC10U6D3V3MX-GP  [C603H38]  166.81 11.51 90 bottom
C2903  SC10U6D3V3MX-GP  [C603H38]  165.44 14.94 270 bottom
C2904  SC10U6D3V3MX-GP  [C603H38]  166.68 16.39 270 bottom
C2905  SC1KP50V2KX-1GP  [C402H22]  149.96 17.81 270 top
C2906  SC10U6D3V3MX-GP  [C603H38]  148.8 15.42 0 bottom
C2907  SC1KP50V2KX-1GP  [C402H22]  149.54 16.51 180 top
C2908  SC10U6D3V3MX-GP  [C603H38]  150.05 9.04 270 bottom
C2909  SC1KP50V2KX-1GP  [C402H22]  153.35 7.7 90 top
C2910  SC1KP50V2KX-1GP  [C402H22]  146.11 7.52 0 top
C3501  SCD1U16V2KX-3GP  [C402H22]  29.81 35.83 90 bottom
C3502  SCD1U16V2KX-3GP  [C402H22]  29.83 34.95 90 bottom
C3507  SCD1U16V2KX-3GP  [C402H22]  23.8 17.01 270 top
C3508  SCD1U16V2KX-3GP  [C402H22]  23.8 16.18 270 top
C3509  SCD1U16V2KX-3GP  [C402H22]  22.97 39.37 270 top
C3515  SC22U6D3V5MX-2GP  [C805H58]  166.1 9.4 180 bottom
C3517  SCD1U16V2KX-3GP  [C402H22]  174.45 24.36 180 top
C3518  SC1U10V2KX-1GP  [C402H22]  175.34 24.36 180 top
C3601  SC22U6D3V5MX-2GP  [C805H58]  18.9 41.02 180 top
C3602  SC22U6D3V5MX-2GP  [C805H58]  17 41.02 180 top
C3604  SC1U10V2KX-1GP  [C402H22]  22.97 40.26 270 top
C3605  SCD1U16V2KX-3GP  [C402H22]  19.34 18.14 90 top
C3606  SC1U10V2KX-1GP  [C402H22]  17.89 35.31 0 top
C3607  SC100U6D3V6MX-GP  [C1206H71]  20.94 41.15 180 top
C4002  SC10U6D3V3MX-GP  [C603H38]  24.16 53.76 270 top
C4003  SC470P50V2KX-3GP  [C402H22]  32.02 50.69 90 top
C4004  SC10U6D3V3MX-GP  [C603H38]  150.74 60.61 180 bottom
C4005  SC10U6D3V3MX-GP  [C603H38]  23.25 49.34 270 top
C4006  SC10U6D3V3MX-GP  [C603H38]  31.7 50.8 0 bottom
C4010  SCD1U16V2KX-3GP  [C402H22]  24.47 51.72 270 top
C4011  SCD1U16V2KX-3GP  [C402H22]  128.84 119.56 0 bottom
C4014  SC1KP50V2KX-1GP  [C402H22]  32.05 51.53 90 top
C4030  SCD1U16V2KX-3GP  [C402H22]  128.22 116.42 0 bottom
C4031  SC1U10V2KX-1GP  [C402H22]  135.01 115.39 270 bottom
C4033  SC1KP50V2KX-1GP  [C402H22]  127.34 114.23 180 bottom
C5501  SC4D7U25V5KX-GP  [C805H54]  96.91 167.24 270 top
C5502  SCD1U16V2KX-3GP  [C402H22]  104.58 167.54 90 top
C5503  SC1KP50V2KX-1GP  [C402H22]  97.11 168.56 270 top
C5504  SCD1U16V2KX-3GP  [C402H22]  106.94 165.23 0 top
C5505  SCD1U16V2KX-3GP  [C402H22]  107.8 165.23 0 top
C5506  SCD1U16V2KX-3GP  [C402H22]  111.23 166.75 0 top
C5507  SCD1U16V2KX-3GP  [C402H22]  112.07 166.75 0 top
C5509  SC1U10V2KX-1GP  [C402H22]  104.58 165.81 270 top
C5510  SC4D7U6D3V3KX-GP  [C603H36]  112.66 177.75 270 top
C5511  SCD1U25V2KX-GP  [C402H22]  97.11 169.39 270 top
C5512  SCD1U16V2KX-3GP  [C402H22]  110.4 166.09 0 top
C5513  SCD1U16V2KX-3GP  [C402H22]  109.53 166.09 0 top
C5514  SC2D2U10V3KX-1GP  [C603H36]  119.39 175.92 270 top
C5515  SC4D7U6D3V3KX-GP  [C603H36]  104.83 161.14 90 top
C5516  SC4D7U6D3V3KX-GP  [C603H36]  99.35 156.62 0 top
C5536  SC1U10V2KX-1GP  [C402H22]  104.58 166.68 270 top
C5538  SCD1U16V2KX-3GP  [C402H22]  104.58 168.4 90 top
C5701  SCD1U16V2KX-3GP  [C402H22]  19.5 51.39 270 top
C5702  SCD1U16V2KX-3GP  [C402H22]  19.5 50.58 270 top
C5703  SCD1U16V2KX-3GP  [C402H22]  19.49 49.71 270 top
C5704  SCD1U16V2KX-3GP  [C402H22]  19.49 48.89 270 top
C5705  SCD1U16V2KX-3GP  [C402H22]  19.5 48.01 270 top
C5706  SCD1U16V2KX-3GP  [C402H22]  19.5 47.2 270 top
C5707  SCD1U16V2KX-3GP  [C402H22]  19.47 46.33 270 top
C5708  SCD1U16V2KX-3GP  [C402H22]  19.47 45.51 270 top
C6001  SCD01U50V2KX-1GP  [C402H22]  169.81 141.18 270 top
C6002  SCD01U50V2KX-1GP  [C402H22]  169.81 139.4 270 top
C6003  SCD01U50V2KX-1GP  [C402H22]  169.81 140.29 270 top
C6004  SCD01U50V2KX-1GP  [C402H22]  169.81 138.51 270 top
C6005  SCD01U50V2KX-1GP  [C402H22]  169.81 140.29 90 bottom
C6006  SCD01U50V2KX-1GP  [C402H22]  169.81 139.4 90 bottom
C6007  SCD01U50V2KX-1GP  [C402H22]  169.81 141.18 90 bottom
C6008  SCD01U50V2KX-1GP  [C402H22]  169.81 138.51 90 bottom
C6009  SC1U10V2KX-1GP  [C402H22]  165.26 44.07 180 top
C6010  SC1U10V2KX-1GP  [C402H22]  167.11 43.64 90 top
C6011  SCD01U50V2KX-1GP  [C402H22]  169.53 40.59 270 bottom
C6012  SC1U10V2KX-1GP  [C402H22]  162.34 37.09 180 bottom
C6013  SCD01U50V2KX-1GP  [C402H22]  151.92 40.95 270 bottom
C6014  SCD01U50V2KX-1GP  [C402H22]  151.92 41.84 270 bottom
C6015  SCD01U50V2KX-1GP  [C402H22]  151.92 43.61 90 bottom
C6016  SCD01U50V2KX-1GP  [C402H22]  169.53 42.37 270 bottom
C6017  SCD01U50V2KX-1GP  [C402H22]  169.53 39.7 270 bottom
C6018  SCD01U50V2KX-1GP  [C402H22]  151.92 42.72 90 bottom
C6019  SCD01U50V2KX-1GP  [C402H22]  169.53 41.48 270 bottom
C6020  SCD1U16V2KX-3GP  [C402H22]  168.99 147.58 0 bottom
C6021  SC10U10V5KX-2GP  [C805H54]  177.07 52.38 90 bottom
C6022  SCD1U16V2KX-3GP  [C402H22]  176.61 49.2 270 bottom
C6023  SC10U10V5KX-2GP  [C805H54]  174.18 50.07 90 bottom
C6024  SC10U10V5KX-2GP  [C805H54]  171.05 148.01 270 top
C6101  SCD1U16V2KX-3GP  [C402H22]  146.34 150.8 180 top
C6102  SC10U6D3V3MX-GP  [C603H38]  146.74 149.25 90 top
C6103  SCD1U16V2KX-3GP  [C402H22]  145.5 150.8 180 top
C6301  SC1U10V2KX-1GP  [C402H22]  57.51 59.01 270 top
C6302  SC4D7U6D3V3KX-GP  [C603H36]  60.92 62.33 180 top
C6303  SCD1U16V2KX-3GP  [C402H22]  52.92 59.31 0 top
C6304  SC4D7U6D3V3KX-GP  [C603H36]  50.02 61.55 180 top
C6305  SCD1U16V2KX-3GP  [C402H22]  58.76 61.88 90 top
C6401  SCD1U16V2KX-3GP  [C402H22]  169.81 181.28 90 top
C6501  SCD1U16V2KX-3GP  [C402H22]  156.03 128.98 0 top
C6502  SCD1U16V2KX-3GP  [C402H22]  156.03 131.52 180 top
C6503  SCD1U16V2KX-3GP  [C402H22]  134.96 22.84 180 bottom
C6504  SCD1U16V2KX-3GP  [C402H22]  131.96 18.59 90 bottom
C6601  SCD1U16V2KX-3GP  [C402H22]  173.36 35.89 0 bottom
C7001  SC10U6D3V3MX-GP  [C603H38]  172.47 46.61 0 bottom
C7002  SCD1U16V2KX-3GP  [C402H22]  175.85 45.14 90 top
C7003  SCD1U16V2KX-3GP  [C402H22]  174.05 45.14 270 top
C9901  SC10U6D3V3MX-GP  [C603H38]  61.81 74.65 90 top
C9902  SCD1U16V2KX-3GP  [C402H22]  55.46 63.02 270 top
C9903  SCD1U16V2KX-3GP  [C402H22]  51.09 62.71 0 top
C9904  SCD1U16V2KX-3GP  [C402H22]  41.97 63.1 90 top
C9905  SCD1U16V2KX-3GP  [C402H22]  61.75 73.56 90 top
CPU1  APOLLO-LAKE-GP-U  [BGA1296M3124H56]  124.9 86.88 20 bottom
D1601  LBAS16LT1G-GP  [SOT23-2D4-312H44]  83.57 67.97 0 top
D2401  RB751V-40H-GP  [SOD323AKH38]  154.03 58.27 270 bottom
D2701  BAT54C-7-F-3-GP  [SOT23-2D4-312H48]  175.22 74.09 270 bottom
D4001  BAT54C-7-F-3-GP  [SOT23-2D4-312H48]  48.39 43.44 270 bottom
D4304  LBAV99LT1G-1-GP  [SOT23-2D4-312H44]  156.14 176.28 270 bottom
D4305  LBAV99LT1G-1-GP  [SOT23-2D4-312H44]  149.69 173.38 90 bottom
D4306  LBAV99LT1G-1-GP  [SOT23-2D4-312H44]  152.03 176.25 270 bottom
D5501  BAT54C-7-F-3-GP  [SOT23-2D4-312H48]  106.89 157.61 90 top
D5502  BAT54C-7-F-3-GP  [SOT23-2D4-312H48]  114.74 157.69 0 top
D5701  LBAW56LT1G-GP  [SOT23-2D4-312H44]  23.25 58.45 180 top
DB1  PAD-ACES-CON10-14-GP  [PAD-87212-1002N]  161.58 87.48 90 bottom
DB3  ACES-CON4-37-GP  [88459-047N]  61.4 41.38 0 top
DCIN1  ACES-CON6-63-GP  [50458-00601-W01]  130.9 182.3 180 top
DCIN2  ACES-CON6-63-GP  [50458-00601-W01]  130.9 182.3 0 bottom
DM1  DDR3-204P-262-GP-U  [AS0A621-J4R6-7H-U]  113.62 34.62 180 bottom
EC1801  SC10P50V2JN-4GP  [C402H22]  107.12 72.95 90 bottom
EC1901  SC10P50V2JN-4GP  [C402H22]  102.69 81.89 110 bottom
EC1902  SC10P50V2JN-4GP  [C402H22]  104.18 80.24 0 top
EC2001  SC10P50V2JN-4GP  [C402H22]  102.39 82.74 110 bottom
EC2002  SC10P50V2JN-4GP  [C402H22]  83.67 65.2 270 top
EC2102  SC10P50V2JN-4GP  [C402H22]  89.64 62.23 270 top
EC2401  AZ5725-01FDR7G-GP  [SOD882-10D6-1H20]  163.05 73.36 270 bottom
EC2402  AZ5725-01FDR7G-GP  [SOD882-10D6-1H20]  167.04 49.05 0 top
EC2403  AZ5725-01FDR7G-GP  [SOD882-10D6-1H20]  166.17 49.05 0 top
EC2501  SC4D7P50V2BN-GP  [C402H22]  56.55 46.13 90 top
EC2502  SC4D7P50V2BN-GP  [C402H22]  63.84 50.14 90 top
EC2503  SC10P50V2JN-4GP  [C402H22]  56.55 48.31 90 top
EC2504  SC4D7P50V2BN-GP  [C402H22]  173.11 32.79 90 top
EC2505  SC10P50V2JN-4GP  [C402H22]  173.11 31.93 90 top
EC2506  SC4D7P50V2BN-GP  [C402H22]  162.9 31.37 0 bottom
EC2702  SC1KP50V2KX-1GP  [C402H22]  165.01 11.43 0 top
EC2703  SC1KP50V2KX-1GP  [C402H22]  162.96 18.26 270 top
EC2704  SC1KP50V2KX-1GP  [C402H22]  160.59 12.24 180 bottom
EC2705  SC1KP50V2KX-1GP  [C402H22]  162.98 19.08 270 top
EC2706  SC1KP50V2KX-1GP  [C402H22]  162.96 19.93 270 top
EC2708  SC22P50V2JN-4GP  [C402H22]  160.43 25.35 90 bottom
EC2709  SC10P50V2JN-4GP  [C402H22]  113.34 165.46 90 top
EC2901  SC1KP50V2KX-1GP  [C402H22]  156.4 24.12 90 top
EC2902  SC1KP50V2KX-1GP  [C402H22]  149.54 20.27 0 top
EC2903  SC1KP50V2KX-1GP  [C402H22]  151.24 19.65 270 top
EC2904  SC1KP50V2KX-1GP  [C402H22]  157.86 20.99 90 top
EC2905  SC100P50V2JN-3GP  [C402H22]  166.7 14.28 0 top
EC2906  SC100P50V2JN-3GP  [C402H22]  169.55 18.29 270 top
EC2907  SC100P50V2JN-3GP  [C402H22]  168.36 14.28 0 top
EC2908  SC100P50V2JN-3GP  [C402H22]  169.12 17.86 0 bottom
EC4001  SCD1U16V2KX-3GP  [C402H22]  164.47 6.68 180 bottom
EC4002  SCD1U16V2KX-3GP  [C402H22]  24.28 54.97 270 top
EC4003  SCD1U16V2KX-3GP  [C402H22]  30.63 50.92 0 bottom
EC4004  SCD1U16V2KX-3GP  [C402H22]  31.87 52.42 90 top
EC4005  SCD1U16V2KX-3GP  [C402H22]  23.35 50.7 270 top
EC4301  SC10U25V5KX-GP  [C805H56]  133.31 174.1 90 top
EC4302  SCD1U25V2KX-GP  [C402H22]  133.23 175.47 90 top
EC4306  SC10P50V2JN-4GP  [C402H22]  148.7 179.53 0 top
EC4307  SCD1U25V2KX-GP  [C402H22]  167.06 174.17 270 bottom
EC4308  SCD1U50V3KX-GP  [C603H36]  167.16 179.2 90 top
EC4309  SC10P50V2JN-4GP  [C402H22]  148.67 177.4 0 top
EC4310  SC10P50V2JN-4GP  [C402H22]  161.7 144.55 0 top
EC4401  SCD1U25V2KX-GP  [C402H22]  153.5 162.59 270 top
EC4402  SCD1U25V2KX-GP  [C402H22]  153.5 163.48 270 top
EC5501  SCD1U25V2KX-GP  [C402H22]  94.93 162.61 270 top
EC5502  SCD1U25V2KX-GP  [C402H22]  94.93 161.72 270 top
EC5503  SCD1U25V2KX-GP  [C402H22]  94.92 160.82 270 top
EC5504  SC22P50V2JN-4GP  [C402H22]  113.34 166.3 270 top
EC5505  SC22P50V2JN-4GP  [C402H22]  115.04 166.3 90 top
EC5506  SC6P50V2CN-1GP  [C402H22]  106.71 173.76 0 top
EC5507  SC33P50V2JN-3GP  [C402H22]  112.76 178.87 270 top
EC5701  SCD1U25V2KX-GP  [C402H22]  14.76 56.29 180 bottom
EC6401  SCD1U16V2KX-3GP  [C402H22]  171.15 172.95 180 bottom
EC6402  SCD1U25V2KX-GP  [C402H22]  170.9 6.05 90 bottom
EC6403  SC1KP50V2KX-1GP  [C402H22]  170.29 172.95 180 bottom
EC6404  SCD1U25V2KX-GP  [C402H22]  170.06 6.89 270 bottom
EC6501  SC33P50V2JN-3GP  [C402H22]  140.47 22.23 0 bottom
EC6502  SC33P50V2JN-3GP  [C402H22]  144.91 18.16 180 bottom
EC6503  SC33P50V2JN-3GP  [C402H22]  139.63 22.23 0 bottom
EC6504  SC33P50V2JN-3GP  [C402H22]  142.37 18.16 180 bottom
EC6505  SC33P50V2JN-3GP  [C402H22]  143.97 31.5 270 top
EC6506  SC33P50V2JN-3GP  [C402H22]  145.7 31.5 90 top
EC8901  SCD1U25V2KX-GP  [C402H22]  156.75 177.32 270 top
EC8902  SCD1U25V2KX-GP  [C402H22]  138.62 172.93 180 top
EC8903  SCD1U25V2KX-GP  [C402H22]  97.21 153.19 270 top
EC8904  SCD1U25V2KX-GP  [C402H22]  117.76 142.75 90 top
EC8905  SCD1U25V2KX-GP  [C402H22]  136.84 158.29 90 top
EC8906  SCD1U25V2KX-GP  [C402H22]  98.28 129.97 90 top
EC8907  SCD1U25V2KX-GP  [C402H22]  99.83 109.04 90 top
EC8908  SCD1U25V2KX-GP  [C402H22]  54.11 57.25 270 top
EC8909  SCD1U25V2KX-GP  [C402H22]  163.68 9.48 90 top
EC8910  SCD1U25V2KX-GP  [C402H22]  144.71 14.56 90 top
EC8911  SCD1U25V2KX-GP  [C402H22]  43.34 23.65 0 top
EC8912  SCD1U25V2KX-GP  [C402H22]  87.92 39.68 180 top
EC8913  SCD1U25V2KX-GP  [C402H22]  86.21 39.68 180 top
EC8914  SCD1U25V2KX-GP  [C402H22]  84.51 39.68 180 top
EC8915  SCD1U25V2KX-GP  [C402H22]  118.85 179.05 90 top
EC8916  SCD1U25V2KX-GP  [C402H22]  97.85 159.23 270 top
EC8917  SCD1U25V2KX-GP  [C402H22]  124.19 162.94 90 top
EC8918  SCD1U25V2KX-GP  [C402H22]  27.92 67.08 0 top
EC8919  SCD1U25V2KX-GP  [C402H22]  53.09 29.52 270 bottom
EC8920  SCD1U25V2KX-GP  [C402H22]  75.98 27.36 0 bottom
EC8921  SCD1U25V2KX-GP  [C402H22]  176.18 133.89 180 bottom
EC8922  SCD1U25V2KX-GP  [C402H22]  175.78 25.66 270 top
EC8923  SCD1U25V2KX-GP  [C402H22]  170.42 9.53 90 top
EC8924  SCD1U25V2KX-GP  [C402H22]  131.46 21.4 180 bottom
EC8925  SCD1U25V2KX-GP  [C402H22]  178.34 52.05 180 top
EC8926  SCD1U25V2KX-GP  [C402H22]  33.56 34.17 90 top
EC8927  SCD1U25V2KX-GP  [C402H22]  149.84 128.68 0 bottom
EC8928  SCD1U25V2KX-GP  [C402H22]  46.36 29.67 180 top
EC8929  SCD1U25V2KX-GP  [C402H22]  143.95 107.27 90 bottom
EC8930  SCD1U25V2KX-GP  [C402H22]  31.83 48.97 90 top
EC8931  SCD1U25V2KX-GP  [C402H22]  32.01 49.84 90 top
ED1201  AZ5725-01FDR7G-GP  [SOD882-10D6-1H20]  92.18 30.86 90 top
ED1202  AZ5725-01FDR7G-GP  [SOD882-10D6-1H20]  87.56 30.84 180 top
ED1803  AZ5725-01FDR7G-GP  [SOD882-10D6-1H20]  125.79 130.28 90 bottom
ED1804  AZ5725-01FDR7G-GP  [SOD882-10D6-1H20]  96.86 90.2 90 bottom
ED1805  AZ5725-01FDR7G-GP  [SOD882-10D6-1H20]  95.59 89.69 180 bottom
ED1806  AZ5725-01FDR7G-GP  [SOD882-10D6-1H20]  126.3 107.85 180 top
ED1807  AZ5725-01FDR7G-GP  [SOD882-10D6-1H20]  104.12 72.01 90 bottom
ED1808  AZ5725-01FDR7G-GP  [SOD882-10D6-1H20]  93.39 90.07 270 bottom
ED1809  AZ5725-01FDR7G-GP  [SOD882-10D6-1H20]  104.28 89.89 270.1 top
ED5701  L05ESDL5V0NA-4-GP  [SLP2510P8-1H22]  16.16 46.61 270 top
ED5702  L05ESDL5V0NA-4-GP  [SLP2510P8-1H22]  16.16 50.12 270 top
ED5703  L05ESDL5V0NA-4-GP  [SLP2510P8-1H22]  15.96 56.03 270 top
ED6401  AZ5725-01FDR7G-GP  [SOD882-10D6-1H20]  170.39 172.98 0 top
ED6601  AZC099-04S-2-GP  [SOT-6H58]  170.29 35.51 90 bottom
EL3503  FILTER-4P-137-GP-U  [L125100-4P-4H28]  20.96 30.15 180 top
EL3504  FILTER-4P-137-GP-U  [L125100-4P-4H28]  21.83 27.05 180 top
EL4301  0R0805-PAD-2-GP-U  [0R0805-PAD-1-U]  133.33 172.21 90 top
EL4302  0R0805-PAD-2-GP-U  [0R0805-PAD-1-U]  133.33 170.31 90 top
EL4303  0R0805-PAD-2-GP-U  [0R0805-PAD-1-U]  138.13 174.7 90 top
EL4304  0R0805-PAD-2-GP-U  [0R0805-PAD-1-U]  138.13 174.7 270 bottom
EL6601  FILTER-4P-137-GP-U  [L125100-4P-4H28]  166.38 34.62 180 bottom
EL6602  FILTER-4P-137-GP-U  [L125100-4P-4H28]  175.29 33.15 90 top
ER3505  0R0402-PAD-2-GP  [0R0402-PAD-1]  27.22 34.88 90 bottom
ER3506  0R0402-PAD-2-GP  [0R0402-PAD-1]  27.23 35.71 90 bottom
ER3509  0R0402-PAD-2-GP  [0R0402-PAD-1]  21.09 16.13 270 top
ER3510  0R0402-PAD-2-GP  [0R0402-PAD-1]  21.09 16.99 270 top
ER3511  0R0402-PAD-2-GP  [0R0402-PAD-1]  21.04 14.12 270 top
ER3512  0R0402-PAD-2-GP  [0R0402-PAD-1]  21.04 14.96 270 top
ER6102  0R0402-PAD-2-GP  [0R0402-PAD-1]  150.81 143.49 0 top
ER6103  0R0402-PAD-2-GP  [0R0402-PAD-1]  149.92 143.49 0 top
EU3501  L05ESDL5V0NA-4-GP  [SLP2510P8-1H22]  22.64 33 90 bottom
EU3502  AZC099-04S-2-GP  [SOT-6H58]  19.16 21.47 0 top
EU3504  L05ESDL5V0NA-4-GP  [SLP2510P8-1H22]  18.14 15.17 90 top
EU5501  AZC099-04S-2-GP  [SOT-6H58]  118.32 168.28 0 top
EU6001  AZ1045-04F-R7G-GP  [DFN10G2510H26]  171.81 41.02 270 bottom
F5501  POLYSW-1D1A24V-GP-U  [POLYSW-4633-UH43]  98.15 163.27 180 top
F5502  POLYSW-D5A6V-1-GP  [POLYSW-2114H50]  115.25 180.88 270 top
F5503  POLYSW-1D1A24V-GP-U  [POLYSW-4633-UH43]  122.59 169.83 180 top
F5701  POLYSW-1D1A6V-9-GP-U  [POLYSW-2114H30]  14.71 58.96 180 bottom
FC3503  SC1P50V2CN-1GP  [C402H22]  23.89 36.14 270 bottom
FC3504  SC1P50V2CN-1GP  [C402H22]  22.15 36.13 90 bottom
FC3505  SC1P50V2CN-1GP  [C402H22]  22.11 29.72 90 bottom
FC3506  SC1P50V2CN-1GP  [C402H22]  23.79 29.73 270 bottom
G1801  GAP-OPEN  [CON2O-U]  104.59 95.26 110 bottom
G6401  GAP-OPEN  [CON2O-U]  169.5 176.23 90 top
G6402  GAP-OPEN  [CON2O-U]  169.5 176.23 270 bottom
H1  HOLE335R115-GP  [HOLE335R115]  135.8 143.35 0 top
H2  HOLE335R115-GP  [HOLE335R115]  14.4 66.8 0 top
H3  HOLE335R115-GP  [HOLE335R115]  21.9 8.3 0 top
H4  HOLE335R115-GP  [HOLE335R115]  173.4 84.3 0 top
H5  HOLE276R91-GP  [HOLE276R91]  143.4 177.8 180 bottom
H6  HOLE335R178-GP  [HOLE335R178]  97.4 73.88 0 top
H7  HOLE335R178-GP  [HOLE335R178]  152.4 73.88 0 top
H8  HOLE335R178-GP  [HOLE335R178]  97.4 99.88 0 top
H9  HOLE335R178-GP  [HOLE335R178]  152.4 99.88 0 top
H10  HOLE384X421R115-GP  [HOLE384X421R115]  177.9 4.1 0 bottom
HDA27  ALC3246-CG-GP-U  [QFN48J6-G465H40]  161.46 20.45 180 bottom
HDD1  STAR-CON12-1-GP  [132F12-010000-A2-R]  177.4 42.3 270 bottom
HDMI1  SKT-HDMI23-168-GP  [SKT-HDMI23-188137-5]  3.7 51.5 90 bottom
HS1  STF236R128H101-4-GP  [STF236R128H101]  120.65 159 180 bottom
IOBD1  ACES-CON30-9-GP-U2  [51519-03001-W02-U2]  177.65 21.3 270 bottom
KB1  PTWO-CON30-10-GP  [196370-30041-3]  173.45 110.08 270 top
KB2  ACES-CON30-29-GP  [50699-03001-W01]  174.95 107.49 270 bottom
KBBL1  ACES-CON4-83-GP  [51678-00401-W01]  162.86 131.27 90 top
KBC24  NPCE985PB1DX-GP-U  [LQFP128H63]  166.45 60.12 180 bottom
L2701  ACMS160808A121RDC05-GP  [L603H38]  151.01 20.34 90 bottom
LCD1  IPEX-CON40-3-GP  [20455-040E-12]  107.83 175.02 20 bottom
LED1  LED-YW-5-GP  [LED3020-3P-19H44]  169.4 1.8 90 bottom
NOREF  -  [unnamed]  184.65 262.26 0 top
NOREF#2  -  [unnamed]  47.23 4.06 0 top
NOREF#3  -  [unnamed]  -3.01 1.62 0 top
NOREF#4  -  [#2]  111.09 237.52 180 top
NOREF#5  *  [unnamed]  139.02 149.91 0 top
NOREF#6  *  [unnamed]  108.26 182.45 0 top
NOREF#7  *  [unnamed]  153.32 121.8 0 top
NOREF#8  -  [#2]  -6.5 72.43 0 top
NOREF#9  -  [#2]  140.44 118.21 0 top
NOREF#10  -  [#2]  169.4 225.3 0 top
NOREF#11  -  [#2]  132.3 4.34 180 top
NOREF#12  -  [#2]  69.61 28.18 0 top
NOREF#13  *  [unnamed]  178.11 170.06 0 top
NOREF#14  -  [unnamed]  126.83 4.16 0 top
NOREF#15  *  [unnamed]  -1.66 260.72 0 top
NOREF#16  -  [unnamed]  53.87 261.54 0 top
NOREF#17  *  [unnamed]  177.58 13.06 0 top
NOREF#18  -  [#2]  -72.99 7.37 0 top
NOREF#19  -  [#2]  48.44 261.36 0 top
NOREF#20  -  [#2]  184.67 58.07 90 top
NOREF#21  -  [#2]  118.47 48.29 0 top
NOREF#22  *  [unnamed]  181.5 262.59 0 top
NOREF#23  *  [unnamed]  146.26 69.62 0 top
NOREF#24  -  [unnamed]  133.47 261.64 0 top
NOREF#25  -  [unnamed]  149.3 2.28 0 top
NOREF#26  -  [unnamed]  7.9 64.3 270 top
NOREF#27  *  [unnamed]  91.88 60.4 0 top
NOREF#28  -  [#2]  36.68 -1.88 0 top
NOREF#29  -  [unnamed]  183.36 5.07 0 top
NOREF#30  -  [#2]  -116.68 -51.57 0 top
NOREF#31  *  [unnamed]  7.05 0.51 0 top
NOREF#32  -  [#2]  144.45 267.6 180 top
NOREF#33  -  [unnamed]  172.9 185.3 0 top
NOREF#34  *  [unnamed]  16.7 4.55 0 top
NOREF#35  *  [unnamed]  -1.66 260.72 180 bottom
NOREF#36  -  [#2]  184.67 72.47 270 bottom
NOREF#37  *  [unnamed]  75.45 30.99 180 bottom
NOREF#38  *  [unnamed]  154.21 120.02 180 bottom
NOREF#39  *  [unnamed]  7.05 0.51 180 bottom
NOREF#40  *  [unnamed]  16.7 4.55 180 bottom
NOREF#41  -  [#2]  84.54 61.42 180 bottom
NOREF#42  -  [#2]  117.69 147.7 180 bottom
NOREF#43  *  [unnamed]  108.52 66.19 180 bottom
NOREF#44  *  [unnamed]  177.68 77.88 180 bottom
NOREF#45  *  [unnamed]  142.76 57.61 180 bottom
NOREF#46  *  [unnamed]  178.11 170.06 180 bottom
NOREF#47  *  [unnamed]  108.26 182.45 180 bottom
NOREF#48  *  [unnamed]  24.11 68.71 180 bottom
NOREF#49  *  [unnamed]  146.29 2.67 180 bottom
NOREF#50  -  [#2]  106 155.86 180 bottom
NOREF#51  *  [unnamed]  98.05 133.56 180 bottom
NOREF#52  *  [unnamed]  181.5 262.59 180 bottom
ODD1  ACES-CON20-30-GP-U1  [51519-02001-W03-U1]  179.6 145.3 90 top
ODD2  ACES-CON20-30-GP-U1  [51519-02001-W03-U1]  179.6 145.3 270 bottom
PC1001  SC22U6D3V3MX-1-GP  [C603H40]  134.86 83.54 290 top
PC1002  SC22U6D3V3MX-1-GP  [C603H40]  139 83.24 90 top
PC1003  SC10U6D3V3MX-GP  [C603H38]  119.39 80.27 200 top
PC1004  SC10U6D3V3MX-GP  [C603H38]  118.14 79.8 200 top
PC1006  SC22U6D3V3MX-1-GP  [C603H40]  129.04 86.74 200 top
PC1007  SC22U6D3V3MX-1-GP  [C603H40]  122.44 83.26 20 top
PC1008  SC22U6D3V3MX-1-GP  [C603H40]  149.71 106.3 180 bottom
PC1009  SC22U6D3V3MX-1-GP  [C603H40]  120 82.43 20 top
PC1010  SC22U6D3V3MX-1-GP  [C603H40]  114.36 94.72 290 top
PC1011  SC22U6D3V3MX-1-GP  [C603H40]  107.3 115.27 90 top
PC1012  SC22U6D3V3MX-1-GP  [C603H40]  110.52 112.93 90 bottom
PC1013  SC22U6D3V3MX-1-GP  [C603H40]  115.4 91.24 290 top
